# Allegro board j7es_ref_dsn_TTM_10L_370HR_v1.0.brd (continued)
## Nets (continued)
MCASP0_AFSX/SPI3_CS2: TPX130.1 U9.AB25(PRG0_PRU0_GPO10)
MCASP0_AXR0/PRG0_RGMII1_RD0: TPX54.1 U9.AF28(PRG0_PRU0_GPO0)
MCASP0_AXR1/PRG0_RGMII1_RD1: TPX5.1 U9.AE28(PRG0_PRU0_GPO1)
MCASP0_AXR2/PRG0_RGMII1_RX_CTL: TPX55.1 U9.AD25(PRG0_PRU0_GPO4)
MCASP0_AXR3: TPX183.1 U9.AC29(PRG0_PRU0_GPO5)
MCASP0_AXR4/PRG0_RGMII1_RXC: TPX29.1 U9.AE26(PRG0_PRU0_GPO6)
MCASP0_AXR5/MCAN9_TX: TPX158.1 U9.AC28(PRG0_PRU0_GPO7)
MCASP0_AXR6/MCAN9_RX: TPX132.1 U9.AC27(PRG0_PRU0_GPO8)
MCASP0_AXR7/PRG0_RGMII1_TD0: TPX28.1 U9.AJ28(PRG0_PRU0_GPO11)
MCASP0_AXR8/PRG0_RGMII1_TD1: TPX100.1 U9.AH27(PRG0_PRU0_GPO12)
MCASP0_AXR9/PRG0_RGMII1_TD2: TPX76.1 U9.AH29(PRG0_PRU0_GPO13)
MCASP0_AXR10/PRG0_RGMII1_TD3: TPX53.1 U9.AG28(PRG0_PRU0_GPO14)
MCASP0_AXR11/PRG0_RGMII1_TX_CTL: TPX75.1 U9.AG27(PRG0_PRU0_GPO15)
MCASP0_AXR12/PRG0_RGMII1_TXC: TPX4.1 U9.AH28(PRG0_PRU0_GPO16)
MCASP0_AXR13/PRG0_PWM0_B2: TPX110.1 U9.AB24(PRG0_PRU0_GPO17)
MCASP1_ACLKX: TPX83.1 U9.AB27(PRG0_PRU1_GPO5)
MCASP1_AFSX/MCAN11_RX: TPX82.1 U9.AA28(PRG0_PRU1_GPO8)
MCASP1_AXR0/PRG0_RGMII2_RD0: TPX129.1 U9.AE29(PRG0_PRU1_GPO0)
MCASP1_AXR1/PRG0_RGMII2_RD1: TPX179.1 U9.AD28(PRG0_PRU1_GPO1)
MCASP1_AXR2/PRG0_RGMII2_RX_CTL: TPX104.1 U9.AD29(PRG0_PRU1_GPO4)
MCASP1_AXR3/PRG0_RGMII2_RXC: TPX154.1 U9.AC26(PRG0_PRU1_GPO6)
MCASP1_AXR5/UART8_RXD: TPX181.1 U9.Y24(PRG0_PRU1_GPO9)
MCASP1_AXR6/UART8_TXD: TPX10.1 U9.AA25(PRG0_PRU1_GPO10)
MCASP1_AXR7/PRG0_RGMII2_TD0: TPX78.1 U9.AG26(PRG0_PRU1_GPO11)
MCASP1_AXR8/PRG0_RGMII2_TD1: TPX79.1 U9.AF27(PRG0_PRU1_GPO12)
MCASP2_ACLKX/SPI3_D1: TPX160.1 U9.AA29(PRG0_PRU1_GPO19)
MCASP2_AFSX/SPI3_D0: TPX159.1 U9.AA26(PRG0_PRU1_GPO18)
MCASP2_AXR3/SPI3_CLK: TPX134.1 U9.Y25(PRG0_PRU1_GPO17)
MCASP6_ACLKR/PRG1_RGMII1_RX_CTL: TPX148.1 U9.AH23(PRG1_PRU0_GPO4)
MCASP6_ACLKX/PRG1_RGMII1_RD0: TPX74.1 U9.AC23(PRG1_PRU0_GPO0)
MCASP6_AFSR/PRG1_RGMII1_RXC: TPX124.1 U9.AD22(PRG1_PRU0_GPO6)
MCASP6_AFSX/PRG1_RGMII1_RD1: TPX98.1 U9.AG22(PRG1_PRU0_GPO1)
MCASP6_AXR0/PRG1_RGMII1_RD2: TPX149.1 U9.AF22(PRG1_PRU0_GPO2)
MCU_ADC0_AIN0: TPX43.1 U9.K25(MCU_ADC0_AIN0)
MCU_ADC0_AIN1: TPX89.1 U9.K26(MCU_ADC0_AIN1)
MCU_ADC0_AIN2: TPX190.1 U9.K28(MCU_ADC0_AIN2)
MCU_ADC0_AIN3: TPX114.1 U9.L28(MCU_ADC0_AIN3)
MCU_ADC0_AIN4: TPX42.1 U9.K24(MCU_ADC0_AIN4)
MCU_ADC0_AIN5: TPX167.1 U9.K27(MCU_ADC0_AIN5)
MCU_ADC0_AIN6: TPX115.1 U9.K29(MCU_ADC0_AIN6)
MCU_ADC0_AIN7: TPX140.1 U9.L29(MCU_ADC0_AIN7)
MCU_ADC1_AIN0: TPX66.1 U9.N23(MCU_ADC1_AIN0)
MCU_ADC1_AIN1: TPX69.1 U9.M25(MCU_ADC1_AIN1)
MCU_ADC1_AIN2: TPX38.1 U9.L24(MCU_ADC1_AIN2)
MCU_ADC1_AIN3: TPX39.1 U9.L26(MCU_ADC1_AIN3)
MCU_ADC1_AIN4: TPX139.1 U9.N24(MCU_ADC1_AIN4)
MCU_ADC1_AIN5: TPX90.1 U9.M24(MCU_ADC1_AIN5)
MCU_ADC1_AIN6: TPX65.1 U9.L25(MCU_ADC1_AIN6)
MCU_ADC1_AIN7: TPX117.1 U9.L27(MCU_ADC1_AIN7)
MCU_ADC_EXT_TRIGGER0: TPX14.1 U9.H26(WKUP_GPIO0_10)
MCU_ADC_EXT_TRIGGER1: TPX118.1 U9.H27(WKUP_GPIO0_11)
MCU_CAN0_STBZ: R2102.1 U9.E28(MCU_SPI0_D1)
MCU_CAN1_STB: TPX324.1 U9.F28(WKUP_GPIO0_2)
MCU_HYPERBUS0_CS1#: R3137.1 U9.E22(MCU_OSPI1_CSN1)
MCU_HYPERBUS0_RESET#: U9.E19(MCU_OSPI0_CSN1)
MCU_HYPERBUS0_RESETO#: R138.2 R3136.1
MCU_I2C0_SCL: R74.2 U9.J26(MCU_I2C0_SCL) U27.32(GPIO1)
MCU_I2C0_SDA: R106.2 U9.H25(MCU_I2C0_SDA) U27.33(GPIO2)
MCU_I3C0_SCL: TPX70.1 U9.D26(MCU_I3C0_SCL)
MCU_I3C0_SDA: TPX94.1 U9.D25(MCU_I3C0_SDA)
MCU_I3C0_SDAPULLEN: TPX116.1 U9.E26(PMIC_POWER_EN0)
MCU_MCAN0_EN: TPX259.1 U9.F26(WKUP_GPIO0_0)
MCU_MCAN0_RX: R2109.1 U9.C29(MCU_MCAN0_RX)
MCU_MCAN0_TX: R2110.1 U9.D29(MCU_MCAN0_TX)
MCU_MCAN1_RX: TPX44.1 U9.G24(WKUP_GPIO0_5)
MCU_MCAN1_TX: TPX15.1 U9.G25(WKUP_GPIO0_4)
MCU_MDIO0_MDC: TPX137.1 U9.F23(MCU_MDIO0_MDC)
MCU_MDIO0_MDIO: TPX13.1 U9.E23(MCU_MDIO0_MDIO)
MCU_OSPI0_CLK: R247.2 R253.1 U24.B2(C)
MCU_OSPI0_CS0#: R153.1 U9.F19(MCU_OSPI0_CSN0) U24.C2(S#)
MCU_OSPI0_D0: R154.2 U9.D20(MCU_OSPI0_D0) U24.D3(DQ0)
MCU_OSPI0_D1: R149.2 U9.G19(MCU_OSPI0_D1) U24.D2(DQ1)
MCU_OSPI0_D2: R161.2 U9.G20(MCU_OSPI0_D2) U24.C4(DQ2/W#)
MCU_OSPI0_D3: R158.2 U9.F20(MCU_OSPI0_D3) U24.D4(DQ3)
MCU_OSPI0_D4: R162.2 U9.F21(MCU_OSPI0_D4) U24.D5(DQ4)
MCU_OSPI0_D5: R156.2 U9.E21(MCU_OSPI0_D5) U24.E3(DQ5)
MCU_OSPI0_D6: R150.2 U9.B22(MCU_OSPI0_D6) U24.E2(DQ6)
MCU_OSPI0_D7: R151.2 U9.G21(MCU_OSPI0_D7) U24.E1(DQ7)
MCU_OSPI0_DQS: R144.2 R152.2 U9.D21(MCU_OSPI0_DQS)
MCU_OSPI0_ECC_FAIL: R164.1 U9.B23(MCU_OSPI1_DQS)
MCU_OSPI0_LBCLKO: R264.2 R3140.1 U24.B1(RFU3)
MCU_OSPI0_RESET_OUT0: R108.1 R137.1
MCU_OSPI0_RESET_OUT0_R: R108.2 R114.1 U18.2(B)
MCU_OSPI1_CLK: R240.2 TPX68.1
MCU_OSPI1_CLK_R: R240.1 U9.F22(MCU_OSPI1_CLK)
MCU_OSPI1_CS0: TPX95.1 U9.C22(MCU_OSPI1_CSN0)
MCU_OSPI1_D0: TPX168.1 U9.D22(MCU_OSPI1_D0)
MCU_OSPI1_D1: TPX93.1 U9.G22(MCU_OSPI1_D1)
MCU_OSPI1_D2: TPX21.1 U9.D23(MCU_OSPI1_D2)
MCU_OSPI1_D3: TPX121.1 U9.C23(MCU_OSPI1_D3)
MCU_PERIPH_RSTZ: R109.1 TPX67.1
MCU_PERIPH_RSTZ_R: R109.2 R115.1 U18.1(A)
MCU_PORZ: TPX166.1 U9.H23(MCU_PORZ)
MCU_PORZ_OUT: R124.1 TP117.1(TP) U9.B28(MCU_PORZ_OUT)
MCU_RESETSTATZ: R113.1 TP116.1(TP) TPX92.1 U9.C27(MCU_RESETSTATZ)
MCU_RESETZ: TPX193.1 U9.D28(MCU_RESETZ)
MCU_RGMII1_INT#: TPX48.1 U9.E25(MCU_SPI0_CS0)
MCU_RGMII1_RD0: TPX80.1 U9.B24(MCU_RGMII1_RD0)
MCU_RGMII1_RD1: TPX87.1 U9.A24(MCU_RGMII1_RD1)
MCU_RGMII1_RD2: TPX88.1 U9.D24(MCU_RGMII1_RD2)
MCU_RGMII1_RD3: TPX107.1 U9.A25(MCU_RGMII1_RD3)
MCU_RGMII1_RX_CTL: TPX61.1 U9.C25(MCU_RGMII1_RX_CTL)
MCU_RGMII1_RXC: TPX64.1 U9.C24(MCU_RGMII1_RXC)
MCU_RGMII1_TD0: TPX106.1 U9.B25(MCU_RGMII1_TD0)
MCU_RGMII1_TD1: TPX108.1 U9.A26(MCU_RGMII1_TD1)
MCU_RGMII1_TD2: TPX131.1 U9.A27(MCU_RGMII1_TD2)
MCU_RGMII1_TD3: TPX187.1 U9.A28(MCU_RGMII1_TD3)
MCU_RGMII1_TX_CTL: TPX156.1 U9.B27(MCU_RGMII1_TX_CTL)
MCU_RGMII1_TXC: TPX105.1 U9.B26(MCU_RGMII1_TXC)
MCU_SAFETY_ERRZ: R120.2 U27.18(GPIO7)
MCU_UART0_CTS#: TPX214.1 U9.H29(WKUP_GPIO0_14)
MCU_UART0_RTS#: TPX215.1 U9.J27(WKUP_GPIO0_15)
MCU_UART0_RXD: TPX258.1 U9.H28(WKUP_GPIO0_13)
MCU_UART0_TXD: TPX319.1 U9.G29(WKUP_GPIO0_12)
MDIO0_MDC: U9.V24(MDIO0_MDC) U2011.1(MDC)
MDIO0_MDIO: U9.V26(MDIO0_MDIO) U2011.36(MDIO)
MLB0_MLBCLK_N: R209.2 TPX351.1 U9.AE2(MLB0_MLBCN)
MLB0_MLBCLK_P: R209.1 TPX352.1 U9.AD2(MLB0_MLBCP)
MLB0_MLBDAT_N: R215.2 TPX333.1 U9.AD3(MLB0_MLBDN)
MLB0_MLBDAT_P: R215.1 TPX334.1 U9.AC3(MLB0_MLBDP)
MLB0_MLBSIG_N: R217.2 TPX354.1 U9.AC1(MLB0_MLBSN)
MLB0_MLBSIG_P: R217.1 TPX353.1 U9.AD1(MLB0_MLBSP)
MMC0_CALPAD: R204.2 U9.AE1(MMC0_CALPAD)
MMC0_CLK: R1203.1 R1204.2 U9.AF1(MMC0_CLK)
MMC0_CMD: R1200.2 U9.AE3(MMC0_CMD) U1017.P5(CMD)
MMC0_DAT0: R1189.2 U9.AG2(MMC0_DAT0) U1017.K2(DAT0)
MMC0_DAT1: R1197.2 U9.AH1(MMC0_DAT1) U1017.N2(DAT1)
MMC0_DAT2: R1188.2 U9.AG3(MMC0_DAT2) U1017.K3(DAT2)
MMC0_DAT3: R1201.2 U9.AF4(MMC0_DAT3) U1017.N3(DAT3)
MMC0_DAT4: R1196.2 U9.AE5(MMC0_DAT4) U1017.N8(DAT4)
MMC0_DAT5: R1190.2 U9.AF3(MMC0_DAT5) U1017.K8(DAT5)
MMC0_DAT6: R1198.2 U9.AG1(MMC0_DAT6) U1017.N9(DAT6)
MMC0_DAT7: R1191.2 U9.AF2(MMC0_DAT7) U1017.K9(DAT7)
MMC0_DS: R3142.1 U9.AE4(MMC0_DS)
MMC0_RSTN: U1033.1(OE)
MMC1_CLK: TPX62.1 U9.P25(MMC1_CLK)
MMC1_CMD: TPX86.1 U9.R29(MMC1_CMD)
MMC1_DAT0: TPX136.1 U9.R24(MMC1_DAT0)
MMC1_DAT1: TPX162.1 U9.P24(MMC1_DAT1)
MMC1_DAT2: TPX111.1 U9.R25(MMC1_DAT2)
MMC1_DAT3: TPX85.1 U9.R26(MMC1_DAT3)
MMC1_SDCD/PCIE2_CLKREQN: R86.2 TPX189.1 U9.P23(MMC1_SDCD)
NTRST: J1011.9(NTRST) R1209.2 RJ1025.3
OSC1_XI: R67.1 U9.P29(OSC1_XI)
OSC1_XO: R77.1 U9.P27(OSC1_XO)
OSPI0_ECC_FAIL/MCU_HYPERBUS0_IN: R164.2 R3139.1 U24.A5(DNU1)
OSPI/HYPER_MUX_SEL: TPX238.1 U9.G27(WKUP_GPIO0_8)
OSPI_DQS_R: R152.1 U24.C3(DQS)
OSPI_RST#: U18.4(Y) U24.A4(RESET#)
PCIE0_RX0_N: TPX379.1 U9.AH19(SERDES0_RX0_N)
PCIE0_RX0_P: TPX378.1 U9.AJ18(SERDES0_RX0_P)
PCIE0_TX0_N: C227.2 TPX381.1
PCIE0_TX0_P: C226.2 TPX380.1
PCIE1_RX0_N: TPX449.1 U9.AH15(SERDES1_RX0_N)
PCIE1_RX0_P: TPX448.1 U9.AJ14(SERDES1_RX0_P)
PCIE1_RX1_N: TPX450.1 U9.AH16(SERDES1_RX1_N)
PCIE1_RX1_P: TPX451.1 U9.AJ15(SERDES1_RX1_P)
PCIE1_TX0_N: C224.2 TPX376.1
PCIE1_TX0_P: C225.2 TPX377.1
PCIE1_TX1_N: C223.2 TPX375.1
PCIE1_TX1_P: C222.2 TPX374.1
PCIE2_RX0_N: TPX455.1 U9.AH13(SERDES2_RX0_N)
PCIE2_RX0_P: TPX454.1 U9.AJ12(SERDES2_RX0_P)
PCIE2_RX1_N: TPX373.1 U9.AH12(SERDES2_RX1_N)
PCIE2_RX1_P: TPX372.1 U9.AJ11(SERDES2_RX1_P)
PCIE2_TX0_N: C213.2 TPX447.1
PCIE2_TX0_P: C212.2 TPX446.1
PCIE2_TX1_N: C221.2 TPX371.1
PCIE2_TX1_P: C220.2 TPX370.1
PG_LM5141: R1141.1 R3147.2 TP1010.1(TP) U1007.21(PG) U1022.6(EN)
PG_LM5175: C1059.2 R1033.2 R1135.1 TP1008.1(TP) U1008.17(PGOOD)
PG_LM53603: R1006.2 TP1005.1(TP) U1001.7(EN) U1005.8(RESETN)
PMIC_MCU_INT#_R: R93.1 U9.G26(WKUP_GPIO0_9)
PMIC_POWER_EN1: U9.G23(PMIC_POWER_EN1)
PMIC_PWR_EN1: R502.1 TP3019.1(TP)
PMIC_REGEN1_3V3_OD: U1008.1(EN/UVLO)
PMICB_EN: R280.2 U29.20(NPWRON/ENABLE)
PMICB_FB3: R3150.1 R3151.1 U29.49(FB_B3)
PMICB_FB4: R3148.1 R3149.1 U29.50(FB_B4)
PORZ: TPX282.1 U9.J24(PORZ)
PRG0_MDIO0_MDC: TPX161.1 U9.AA27(PRG0_MDIO0_MDC)
PRG0_MDIO0_MDIO: TPX133.1 U9.Y26(PRG0_MDIO0_MDIO)
PRG0_PWM0_TZ_OUT: TPX184.1 U9.AB28(PRG0_PRU0_GPO19)
PRG0_RGMII1_RD2: TPX30.1 U9.AE27(PRG0_PRU0_GPO2)
PRG0_RGMII1_RD3: TPX6.1 U9.AD26(PRG0_PRU0_GPO3)
PRG0_RGMII2_RD2: TPX103.1 U9.AD27(PRG0_PRU1_GPO2)
PRG0_RGMII2_RD3: TPX180.1 U9.AC25(PRG0_PRU1_GPO3)
PRG0_RGMII2_TD2: TPX31.1 U9.AF26(PRG0_PRU1_GPO13)
PRG0_RGMII2_TD3: TPX7.1 U9.AE25(PRG0_PRU1_GPO14)
PRG1_RGMII1_RD3: TPX174.1 U9.AJ23(PRG1_PRU0_GPO3)
PRG1_UART0_RTS#: TPX155.1 U9.AD21(PRG1_PRU0_GPO10)
PWR_SW_CNTL_DSI0: R3060.1 U3011.3(IN)
RESET_REQZ: TPX192.1 U9.C28(RESET_REQZ)
RESETSTATZ: R225.1 TPX208.1 U9.T6(RESETSTATZ)
RGMII5_RD0: U9.T23(RGMII5_RD0) U2011.26(RX_D0)
RGMII5_RD1: U9.R23(RGMII5_RD1) U2011.25(RX_D1)
RGMII5_RD2: U9.U24(RGMII5_RD2) U2011.24(RX_D2)
RGMII5_RD3: U9.U27(RGMII5_RD3) U2011.23(RX_D3)
RGMII5_RX_CTL: U9.U26(RGMII5_RX_CTL) U2011.15(RX_DV/CRS_DIV/RX_CTRL)
RGMII5_RXC: U9.U25(RGMII5_RXC) U2011.27(RX_CLK)
RGMII5_TD0: U9.U28(RGMII5_TD0) U2011.33(TX_D0)
RGMII5_TD1: U9.V27(RGMII5_TD1) U2011.32(TX_D1)
RGMII5_TD2: U9.V29(RGMII5_TD2) U2011.31(TX_D2)
RGMII5_TD3: U9.V28(RGMII5_TD3) U2011.30(TX_D3)
RGMII5_TX_CTL: U9.U23(RGMII5_TX_CTL) U2011.29(TX_EN/TX_CTRL)
RGMII5_TXC: U9.U29(RGMII5_TXC) U2011.28(TX_CLK)
SEL_SDIO_3V3_1V8N: U9.W4(SPI1_CS1)
SERDES0_REXT: R207.1 U9.AE18(SERDES0_REXT)
SERDES1_REXT: R206.1 U9.AE13(SERDES1_REXT)
SERDES2_REXT: R216.1 U9.AD13(SERDES2_REXT)
SERDES3_REXT: R205.1 U9.AE8(SERDES3_REXT)
SERDES4_REXT: R236.1 U9.F9(SERDES4_REXT)
SERDES4_RX0_N: TP43.1(TP) U9.D9(SERDES4_RX0_N)
SERDES4_RX0_P: TP42.1(TP) U9.C10(SERDES4_RX0_P)
SERDES4_RX1_N: TP36.1(TP) U9.D8(SERDES4_RX1_N)
SERDES4_RX1_P: TP35.1(TP) U9.C9(SERDES4_RX1_P)
SERDES4_RX2_N: TP39.1(TP) U9.D6(SERDES4_RX2_N)
SERDES4_RX2_P: TP37.1(TP) U9.C7(SERDES4_RX2_P)
SERDES4_RX3_N: TP40.1(TP) U9.D5(SERDES4_RX3_N)
SERDES4_RX3_P: TP38.1(TP) U9.C6(SERDES4_RX3_P)
SGMII2_RX0_N: TPX443.1 U9.AH18(SERDES0_RX1_N)
SGMII2_RX0_P: TPX442.1 U9.AJ17(SERDES0_RX1_P)
SGMII2_TX0_N: C215.2 TPX441.1
SGMII2_TX0_P: C214.2 TPX440.1
SOC_EMU0: J1011.19(TRD0.1) R1206.2 U9.C26(EMU0)
SOC_EMU1: J1011.21(TRD0.2) R1207.2 U9.B29(EMU1)
SOC_EXTINTN: R43.1 TPX206.1 U9.AC18(EXTINTN)
SOC_I2C2_SCL: R54.2 TPX296.1 U9.AA1(SPI0_CLK)
SOC_I2C2_SDA: R25.2 TPX203.1 U9.AB5(SPI0_D0)
SOC_MCU_OSPI0_CLK_R: R247.1 U9.E20(MCU_OSPI0_CLK)
SOC_MCU_OSPI0_LBCLKO_R: R264.1 U9.C21(MCU_OSPI0_LBCLKO)
SOC_PORZ_OUT: R80.1 TPX278.1 U9.U1(PORZ_OUT)
SOC_PWR_EN: R3147.1 TP128.1(TP) U27.20(NPWRON/ENABLE)
SOC_SAFETY_ERRZ: R56.2 TPX230.1
SOC_SAFETY_ERRZ_27020508: R276.1
SOC_SERDES0_REFCLK_N: R203.1 TPX392.1 U9.AE17(PCIE_REFCLK0N)
SOC_SERDES0_REFCLK_P: R213.1 TPX393.1 U9.AD16(PCIE_REFCLK0P)
SOC_SERDES1_REFCLK_N: R202.1 TPX423.1 U9.AE14(PCIE_REFCLK1N)
SOC_SERDES1_REFCLK_P: R208.1 TPX422.1 U9.AD15(PCIE_REFCLK1P)
SOC_SERDES2_REFCLK_N: R201.1 TPX427.1 U9.AE11(PCIE_REFCLK2N)
SOC_SERDES2_REFCLK_P: R214.1 TPX426.1 U9.AD12(PCIE_REFCLK2P)
SOC_SERDES4_REFCLK_N: TPX396.1 U9.E7(SERDES4_REFCLK_N)
SOC_SERDES4_REFCLK_P: TPX397.1 U9.E8(SERDES4_REFCLK_P)
SOC_TCK: J1011.3(TCK) R1208.2 R3135.2 U9.E29(TCK)
SOC_TDI: U9.V1(TDI) U131.4(O)
SOC_TDO: U9.V3(TDO) U130.2(I)
SOC_TMS: R1219.2 U9.V2(TMS) U129.4(O)
SOC_TRST#: RJ1025.2 U9.F24(TRSTN)
SOC_WKUP_I2C0_SCL: R105.2 U9.J25(WKUP_I2C0_SCL) U27.31(SCL_I2C1/SCK_SPI) U29.31(SCL_I2C1/SCK_SPI) U1011.6(SCL)
SOC_WKUP_I2C0_SDA: R121.2 U9.H24(WKUP_I2C0_SDA) U27.30(SDA_I2C1/SDI_SPI) U29.30(SDA_I2C1/SDI_SPI) U1011.5(SDA)
SPI3_CS0: TPX34.1 U9.AA24(PRG0_PRU1_GPO7)
SYS_IRQZ: TPX237.1 U9.G28(WKUP_GPIO0_7)
SYS_MCU_PWRDN: TPX211.1 U9.E24(MCU_SPI0_D0)
TIMER_IO0: TPX315.1 U9.V6(TIMER_IO0)
TRD1_N: C2029.1 JZ2000.2 R2025.1
TRD1_P: C2030.1 JZ2000.1 R2027.1
TRD_N: C2028.1 L2005.1 U2011.13(TRD_N)
TRD_P: C2031.1 L2007.1 U2011.12(TRD_P)
TRSTPD: J1011.8(TRSTPD) R1221.1 RJ1025.1
UART0_CTS#: TPX313.1 U9.Y3(SPI1_CS0)
UART0_RTS#: TPX274.1 U9.AA2(SPI0_CS0)
UART0_RXD: TPX337.1 U9.AB2(UART0_RXD)
UART0_TXD: TPX226.1 U9.AB3(UART0_TXD)
UART1_RXD: TPX249.1 U9.AA4(UART1_RXD)
UART1_TXD: TPX312.1 U9.AB4(UART1_TXD)
UART2_RXD: TPX298.1 U9.Y1(SPI1_CLK)
UART2_TXD: TPX248.1 U9.Y5(SPI1_D0)
UB981_CLKIN: R3102.2 R3103.2 R3104.2 TP3014.1(TP) U3019.41(REFCLK0)
UB981_CLKIN_25MHZ: R3104.1 U3020.3(OUTPUT)
UB981_DOUT0_N: C3121.2 FL3030.4
UB981_DOUT0_P: C3119.2 FL3030.1
UB981_GPIO0: U3019.14(GPIO0)
UB981_GPIO1: U3019.15(GPIO1)
UB981_GPIO2: U3019.38(I2S_DC/GPIO2)
UB981_GPIO3: U3019.39(I2S_DD/GPIO3)
UB981_IDX: R3112.1 R3113.2 U3019.19(IDX)
UB981_INTB: R3114.2 R3115.1 U3019.30(INTB)
UB981_MODE_SEL0: R3066.2 R3067.1 U3019.18(MODE_SEL0)
UB981_MODE_SEL1: R3065.2 R3111.1 U3019.32(MODE_SEL1)
UB981_PDB: R3110.1 U3019.31(PDB)
UB981_REM_INTB: R3105.1 U3019.10(REM_INTB)
UFS0_REF_CLK: R168.1 TPX390.1
UFS0_REF_CLK_R: R168.2 U9.AE6(UFS0_REF_CLK)
UFS0_RST#: TPX391.1 U9.AD6(UFS0_RSTN)
UFS0_RX0_N: TPX386.1 U9.AH3(UFS0_RX_DN0)
UFS0_RX0_P: TPX387.1 U9.AJ2(UFS0_RX_DP0)
UFS0_RX1_N: TPX388.1 U9.AH4(UFS0_RX_DN1)
UFS0_RX1_P: TPX389.1 U9.AJ3(UFS0_RX_DP1)
UFS0_TX0_N: TPX385.1 U9.AG6(UFS0_TX_DN0)
UFS0_TX0_P: TPX384.1 U9.AF7(UFS0_TX_DP0)
UFS0_TX1_N: TPX383.1 U9.AG5(UFS0_TX_DN1)
UFS0_TX1_P: TPX382.1 U9.AF6(UFS0_TX_DP1)
USB0_CS: R1010.1
USB0_DATA_N: U9.AJ5(USB0_DM) U1001.4(DM_OUT)
USB0_DATA_P: U9.AH6(USB0_DP) U1001.5(DP_OUT)
USB0_DRVVBUS: R1007.1 R1008.1 R1011.1 U9.U6(USB0_DRVVBUS)
USB0_ID: R3122.1 U9.AC6(USB0_ID)
USB0_IMON: C1017.1 R1005.1 TP1002.1(TP) U1001.1(IMON)
USB0_RCALIB: R218.1 U9.AB6(USB0_RCALIB)
USB0_STATUS: R1001.1 U1001.17(STATUS)
USB0_VBUS_OCN: R1002.1 U1001.18(FAULT)
USB0_VBUS_SOC: R169.2 R170.2 U9.AC7(USB0_VBUS)
USB1_CS: C1194.1 R1127.2 R1130.1
USB1_DM: FL1001.1 U1001.14(DM_IN)
USB1_DP: FL1001.4 U1001.13(DP_IN)
USB1_DRVVBUS: Q1001.2(G2) R1009.1 U9.V4(MCAN1_TX)
USB1_HUB_D_N: U9.AH7(USB1_DM) U1002.12(D-)
USB1_HUB_D_P: U9.AJ6(USB1_DP) U1002.11(D+)
USB1_ID: R3123.1 U9.AD7(USB1_ID)
USB1_RCALIB: R210.1 U9.AD9(USB1_RCALIB)
USB1_VBUS: C1006.2 J1001.1(VBUS) R4.1 U1002.2(VBUS_CON) U1002.3(VBUS_SON)
USB1_VBUS_SOC: R1.1 R4.2 U9.AD8(USB1_VBUS)
USB2_DM: FL1000.4 U1002.5(VD-)
USB2_DP: FL1000.1 U1002.6(VD+)
USBC_DIR: TPX294.1 U9.W3(MCAN1_RX)
USBC_SS_RX1_N: FL3028.4 U9.AH10(SERDES3_RX1_N)
USBC_SS_RX1_P: FL3028.1 U9.AJ9(SERDES3_RX1_P)
USBC_SS_RX2_N: FL1002.4 U9.AH9(SERDES3_RX0_N)
USBC_SS_RX2_P: FL1002.1 U9.AJ8(SERDES3_RX0_P)
USBC_SS_TX1_N: C219.2 FL3029.4
USBC_SS_TX1_P: C218.2 FL3029.1
USBC_SS_TX2_N: C217.2 FL1003.4
USBC_SS_TX2_P: C216.2 FL1003.1
VCAM_9V0: C234.1 C249.1 C3129.1 C3130.1 C3135.1 C3136.1 C3141.1 C3142.1 L51.2 L2018.2 L2024.2 L2030.2
VCAM_CSI: U3022.21(VDD_CSI0) U3022.33(VDD_CSI1)
VCAM_FPD: U3022.52(VDD_FPD1) U3022.61(VDD_FPD2)
VCAM_VDD18: U3022.1(VDD18_P3) U3022.2(VDD18_P2) U3022.47(VDD18_P1) U3022.48(VDD18_P0)
VCAM_VDD18_FPD: U3022.49(VDD18_FPD0) U3022.55(VDD18_FPD1) U3022.58(VDD18_FPD2) U3022.64(VDD18_FPD3)
VCAM_VDDA18: U3022.32(VDDA18A)
VCAM_VDDL: U3022.13(VDDL1) U3022.44(VDDL2)
VCAP_MCU_VDDS0: C372.1 U9.K23(CAP_VDDS0_MCU)
VCAP_MCU_VDDS1: C377.1 U9.J18(CAP_VDDS1_MCU)
VCAP_MCU_VDDS2: C379.1 U9.J19(CAP_VDDS2_MCU)
VCAP_VDDS0: C307.1 U9.U7(CAP_VDDS0)
VCAP_VDDS1: C278.1 U9.AB21(CAP_VDDS1)
VCAP_VDDS2: C291.1 U9.Y18(CAP_VDDS2)
VCAP_VDDS3: C293.1 U9.W21(CAP_VDDS3)
VCAP_VDDS4: C281.1 U9.AA22(CAP_VDDS4)
VCAP_VDDS5: C325.1 U9.R22(CAP_VDDS5)
VCAP_VDDS6: C306.1 U9.V22(CAP_VDDS6)
VDA_DLL_0V8: C512.1 FL6.1 FL15.1 FL29.1 U27.9(VOUT_LDO3)
VDA_MCU_1V8: C104.1 C111.1 C122.1 C131.1 C296.1 C314.1 C348.1 C349.1 C369.1 C370.1 C425.1 C511.1 R272.2 R493.2 U9.G18(VDDA_MCU_PLLGRP0) U9.H22(VDDA_WKUP) U9.M23(VDDA_ADC1) U9.N22(VDDA_ADC0) U9.P21(VDDA_MCU_TEMP) U9.P22(VDDA_POR_WKUP) U27.7(VOUT_LDO4)
VDA_PLL_1V8: C105.1 C112.1 C238.1 C239.1 C295.1 C300.1 C313.1 C428.1 C429.1 C543.1 U9.H9(VDDA_TEMP2_3) U9.L12(VDDA_PLLGRP3) U9.M17(VDDA_PLLGRP2) U9.P9(VDDA_PLLGRP5) U9.R11(VDDA_PLLGRP4) U9.R21(VDDS_OSC1) U9.W15(VDDA_TEMP0_1) U9.W17(VDDA_PLLGRP1) U9.W18(VDDA_PLLGRP6) U9.Y20(VDDA_PLLGRP0) U29.7(VOUT_LDO4)
VDA_USB_3V3: C34.1 C35.1 C545.1 U9.AB10(VDDA_3P3_USB) U29.11(VOUT_LDO2)
VIO_3V3: R1033.1
VMON_VEXT: TP127.1(TP) U9.V19(VMON_IR_VEXT)
VMON_VSYS: C132.1 R84.2 R87.1 U9.M26(VMON_ER_VSYS)
VOSNS: C1061.2 R1039.2 U1008.12(VOSNS)
VOUT0_DATA0/PRG1_RGMII2_RD0: TPX150.1 U9.AE22(PRG1_PRU1_GPO0)
VOUT0_DATA1/PRG1_RGMII2_RD1: TPX126.1 U9.AG23(PRG1_PRU1_GPO1)
VOUT0_DATA2/PRG1_RGMII2_RD2: TPX177.1 U9.AF23(PRG1_PRU1_GPO2)
VOUT0_DATA3/PRG1_RGMII2_RD3: TPX127.1 U9.AD23(PRG1_PRU1_GPO3)
VOUT0_DATA4/PRG1_RGMII2_RX_CTL: TPX101.1 U9.AH24(PRG1_PRU1_GPO4)
VOUT0_DATA5/MCAN6_RX: TPX175.1 U9.AG21(PRG1_PRU1_GPO5)
VOUT0_DATA6/PRG1_RGMII2_RXC: TPX151.1 U9.AE23(PRG1_PRU1_GPO6)
VOUT0_DATA7/MCAN7_TX: TPX50.1 U9.AC21(PRG1_PRU1_GPO7)
VOUT0_DATA8/MCAN7_RX: TPX186.1 U9.Y23(PRG1_PRU1_GPO8)
VOUT0_DATA9/PRG1_UART0_RXD: TPX125.1 U9.AF21(PRG1_PRU1_GPO9)
VOUT0_DATA10/PRG1_UART0_TXD: TPX58.1 U9.AB23(PRG1_PRU1_GPO10)
VOUT0_DATA11/PRG1_RGMII2_TD0: TPX26.1 U9.AJ25(PRG1_PRU1_GPO11)
VOUT0_DATA12/PRG1_RGMII2_TD1: TPX73.1 U9.AH25(PRG1_PRU1_GPO12)
VOUT0_DATA13/PRG1_RGMII2_TD2: TPX25.1 U9.AG25(PRG1_PRU1_GPO13)
VOUT0_DATA14/PRG1_RGMII2_TD3: TPX3.1 U9.AH26(PRG1_PRU1_GPO14)
VOUT0_DATA15/PRG1_RGMII2_TX_CTL: TPX27.1 U9.AJ27(PRG1_PRU1_GPO15)
VOUT0_DATA16/PRG1_RGMII1_TD0: TPX178.1 U9.AF24(PRG1_PRU0_GPO11)
VOUT0_DATA17/PRG1_RGMII1_TD1: TPX77.1 U9.AJ24(PRG1_PRU0_GPO12)
VOUT0_DATA18/PRG1_RGMII1_TD2: TPX102.1 U9.AG24(PRG1_PRU0_GPO13)
VOUT0_DATA19/PRG1_RGMII1_TD3: TPX153.1 U9.AD24(PRG1_PRU0_GPO14)
VOUT0_DATA20/PRG1_RGMII1_TX_CTL: TPX128.1 U9.AC24(PRG1_PRU0_GPO15)
VOUT0_DATA21/PRG1_RGMII1_TXC: TPX152.1 U9.AE24(PRG1_PRU0_GPO16)
VOUT0_DATA22/MCAN4_RX: TPX147.1 U9.AJ20(PRG1_PRU0_GPO8)
VOUT0_DATA23/SPI6_CS1: TPX72.1 U9.AG20(PRG1_PRU0_GPO9)
VOUT0_DE/SPI6_CLK: TPX63.1 U9.AC22(PRG1_PRU1_GPO17)
VOUT0_EXTPCLKIN/MCAN6_TX: TPX173.1 U9.AH21(PRG1_PRU0_GPO19)
VOUT0_HSYNC/PRG1_RGMII2_TXC: TPX2.1 U9.AJ26(PRG1_PRU1_GPO16)
VOUT0_PCLK/SPI6_D1: TPX176.1 U9.AH22(PRG1_PRU1_GPO19)
VOUT0_VSYNC/SPI6_D0: TPX123.1 U9.AJ22(PRG1_PRU1_GPO18)
VPFE0_DATA6/MCAN5_TX: TPX97.1 U9.AJ21(PRG1_PRU0_GPO17)
VPFE0_DATA7/MCAN5_RX: TPX99.1 U9.AE21(PRG1_PRU0_GPO18)
VPFE0_DATA11/PRG1_MDIO0_MDIO: TPX1.1 U9.AD19(PRG1_MDIO0_MDIO)
VPFE0_DATA12/PRG1_MDIO0_MDC: TPX49.1 U9.AD18(PRG1_MDIO0_MDC)
VPP_EFUSE_1V8: C57.1(INPUT) C57.3(OUTPUT) C58.1(INPUT) C58.3(OUTPUT) C279.1 C385.1 U9.AB11(VPP_CORE) U9.F17(VPP_MCU)
VRTC_LEOA_1V8: C510.1 U27.3(VOUT_LDOVRTC)
VRTC_LEOB_1V8: C542.1 R3144.1 U29.3(VOUT_LDOVRTC)
VSYS_3V3: C86.1 C88.1 C1044.1 C1045.1 C1136.1 C1205.1 C3145.1 L1005.2 L1023.1 R84.1 R472.1 R625.1 R1022.2 R1023.2 R1141.2 U6.1(VIN1) U6.2(VIN2) U6.4(VBIAS) U103.5(D) U129.5(VCC) U130.5(VCC) U131.5(VCC) U1022.4(ILM) U1022.8(VIN)
VSYS_5V0: C1145.1 C1146.1 C1161.1 C2121.1 R1071.2 R1074.2 TP1037.1(TP) U1007.16(VCCX) U1022.2(VOUT) U2007.3(VCC)
VSYS_10V5: C1182.1 C1183.1 L1040.2 R1106.2 TP1040.1(TP) U1008.24(BIAS)
VSYS_16V0: C1007.2 C1010.1 C1015.2 C1032.1 C1034.1 C1187.1 C1200.2 C1201.1 C1202.1 J1010.1 Q1006.5(D) R1038.2 R1039.1 R1110.1 TP1006.1(TP) U1005.12(VIN1) U1005.13(VIN2) U1027.7(VIN)
VSYS_SENSE: D2.1(CATHODE) R473.2 U27.51(VSYS_SENSE)
VUB941_1V1: C3054.1 C3061.1 C3063.1 FL3012.1 FL3013.1 FL3014.1
VUSB_5V0: C1011.1 C1012.1 C1016.1 C1018.1 C1020.1 C1024.1 C1194.2 C1197.1 L1002.2 R1006.1 R1125.1 R1127.1 R1137.2 TP1001.1(TP) U1001.2(IN#2) U1001.3(IN#3) U1002.14(VBUS_SYS#14) U1002.15(VBUS_SYS#15)
WKUP_GPIO0_6: TPX18.1 U9.F29(WKUP_GPIO0_6)
WKUP_GPIO0_52: TPX253.1 U9.E27(MCU_SPI0_CLK)
WKUP_LFOSC_XI: R88.1 R281.1 U9.N28(WKUP_LFOSC0_XI)
WKUP_LFOSC_XO: R89.1 U9.N26(WKUP_LFOSC0_XO)
WKUP_OSC0_XIN: C135.1 U9.M29(WKUP_OSC0_XI) Y3.3
WKUP_OSC0_XOUT: C136.1 U9.M27(WKUP_OSC0_XO) Y3.1
WKUP_UART0_RXD: TPX191.1 U9.J29(WKUP_UART0_RXD)
WKUP_UART0_TXD: TPX165.1 U9.J28(WKUP_UART0_TXD)
N22073312: R1203.2 U1017.P6(CLK)
N23139394: D1.3(C) R170.1 R171.2
N23154802: R120.1 U9.D27(MCU_SAFETY_ERRORN)
N24377130: R56.1 U9.U4(SOC_SAFETY_ERRORN)
N24594267: R137.2 R138.1 U9.A23(MCU_OSPI1_LBCLKO)
N27191474: R471.2 U27.52(OVPGDRV)
N27191486: R471.1 U103.4(GATE)
N27191539: R472.2 R473.1
N28200806: C125.1 R88.2 Y2.2
N28200825: C124.1 R89.2 Y2.1
N28200987: C110.1 R67.2 Y1.3
N28201033: C114.1 R77.2 Y1.1
N28832809: C3125.2 R3124.1
N28833063: C228.1 C3126.1 L40.2 L51.1 R3125.2
N28833077: L27.2 L40.1 R132.2 R3125.1
N28833083: L27.1 L62.2 R132.1
N28833091: L61.2 L62.1
N28833093: L60.2 L61.1
N28833539: C3124.2 L60.1 P5.1
N28846480: L2021.2 L2022.1 R3126.1
N28846484: L2022.2 L2023.1 R3126.2 R3127.1
N28846490: C3127.1 C3128.1 L2018.1 L2023.2 R3127.2
N28846519: C3131.2 L2019.1 P6.1
N28846523: L2019.2 L2020.1
N28846525: L2020.2 L2021.1
N28846680: C3132.2 R3128.1
N28847093: L2027.2 L2028.1 R3129.1
N28847097: L2028.2 L2029.1 R3129.2 R3130.1
N28847103: C3133.1 C3134.1 L2024.1 L2029.2 R3130.2
N28847132: C3137.2 L2025.1 P7.1
N28847136: L2025.2 L2026.1
N28847138: L2026.2 L2027.1
N28847293: C3138.2 R3131.1
N28847739: L2033.2 L2034.1 R3132.1
N28847743: L2034.2 L2035.1 R3132.2 R3133.1
N28847749: C3139.1 C3140.1 L2030.1 L2035.2 R3133.2
N28847778: C3143.2 L2031.1 P8.1
N28847782: L2031.2 L2032.1
N28847784: L2032.2 L2033.1
N28847939: C3144.2 R3134.1
N28898333: J1011.1(VREF_DBG) J1011.12(VREF_TR) R3143.2
N28898472: J1011.7(RTCK) R3135.1
N28898495: J1011.15(TGT_DETECT) R1205.2
N28916086: Q13.D R625.2 U129.1(OE) U130.1(OE) U131.1(OE)
N28916647: R3136.2 U24.A2(RFU1)
N28916666: R3137.2 R3138.1 U24.A3(RFU2)
N28964551: R3141.1 R3142.2 U1017.K5(DS)
N28998069: TP3015.1(TP) U9.F13(TEMP_DIODE_P)
N29139280: R3144.2 U29.40(OSC32KCAP)
N29153603: R3148.2 TP3020.1(TP)
N29154086: R3150.2 TP3021.1(TP)
N30074897: R1133.1 U1002.16(IADJ)
N30074992: R1134.2 TP1003.1(TP) U1002.10(FLT)
N30075038: Q1001.6(D2) R1125.2 U1002.7(VEN)
N30075044: R1126.2 U1002.8(DEN)
N30411655: R1164.1 TP1018.1(TP) U1011.7(WP)
N30703324: C1005.1 R1000.2 U1001.12(BIAS)
N30703458: R1003.1 U1001.19(ILIM_LO)
N30703463: R1004.1 U1001.20(ILIM_HI)
N30746595: RJ1000.2 U1001.10(OVP_SEL)
N30808408: L1023.2 U1022.7(SW)
N30809211: C1161.2 R1071.1 R1072.2 U1022.3(FB)
N30811250: R1109.1 R1110.2 RJ1013.2 U1027.5(EN/SYNC)
N30811520: C1190.1 U1027.3(VCC)
N30812987: C1189.1 U1027.2(BOOT)
N30812990: C1189.2 R1091.1
N30812993: L1040.1 R1091.2 U1027.1(SW)
N30813342: C1191.1 R1107.1 R1108.1 U1027.4(FB)
N30813649: C1191.2 R1106.1 R1107.2
N30821669: R1074.1 U1022.5(PG)
N31193882: Q1005.4(G) R1014.1
N31194203: Q1003.4(G) R1020.1
N31194290: Q1004.4(G) R1021.2
N31194295: Q1006.4(G) R1015.2
N31194655: D1008.1(CATHODE) R1034.1
N31194670: C1063.1 R1034.2 U1008.2(VIN)
N31194787: C1049.1 D1007.1(K) U1008.26(BOOT1)
N31194818: C1046.2 D1003.1(CATHODE) D1005.1(K) U1008.20(BOOT2)
N31196095: C1053.2 R1030.1 U1008.15(CSG)
N31196104: C1053.1 R1031.1 U1008.16(CS)
N31196146: C1069.1 U1008.7(SLOPE)
N31196169: R1046.1 U1008.5(DTH)
N31196187: C1071.2 R1042.1 U1008.6(RT/SYNC)
N31196205: R1040.1 R1045.1 U1008.4(MODE)
N31196259: C1065.1 R1036.2 U1008.9(COMP)
N31196266: C1064.1 R1036.1
N31197066: C1070.1 U1008.8(SS)
N31197134: C1062.2 R1037.2 U1008.3(VISNS)
N31197473: R1035.2 R1038.1 TP1012.1(TP)
N31206842: Q1002.4(G) U1006.2(GT PULL DWN) U1006.6(GATE DRV)
N31206856: C1029.1 U1006.1(VCAPL)
N31206860: C1029.2 U1006.7(VCAPH)
N31206880: C1021.1 C1022.1 L1003.1 L1004.1 Q1002.5(D1) R1131.2 U1006.8(CATHODE)
N31207093: D1018.2(ANODE) D1019.2(ANODE)
N31207095: DS1000.2(ANODE) R1131.1
N31208453: R1139.2 U1007.13(HO)
N31208462: R1140.1 U1007.14(HOL)
N31208471: R1144.2 U1007.8(LO)
N31208480: R1145.1 U1007.7(LOL)
N31208503: Q1008.4(G) R1144.1 R1145.2
N31208524: Q1007.4(G) R1139.1 R1140.2
N31208551: C1037.1 C1204.2 D1020.1(CATHODE) L1005.1 Q1007.1(S) Q1008.5(D) R1017.1 U1007.12(SW)
N31208672: C1037.2 D1004.1(CATHODE) U1007.11(HB)
N31208960: C1204.1 R1152.1
N31209649: C1033.2 R1017.2 R1018.1 U1007.18(CS)
N31209654: C1033.1 R1018.2 R1022.1 U1007.17(VOUT)
N31222073: C1047.2 R1142.1 R1143.1 U1007.23(EN)
N31222132: C1039.2 R1026.1
N31222198: C1038.1 R1026.2 U1007.20(COMP)
N31222241: C1050.2 U1007.24(RES)
N31222246: C1041.2 U1007.22(SS)
N31222265: R1028.1 R1029.2 U1007.6(OSC)
N31222285: C1052.2 R1027.1 U1007.5(DITH)
N31222303: R1147.2 U1007.4(RT)
N31222717: R1023.1 R1024.2
N31223527: L1002.1 R1013.2 R1136.1 R1138.1 U1005.1(SW1) U1005.2(SW2)
N31223584: C1026.1 R1137.1 U1005.5(BIAS)
N31223889: C1025.2 R1013.1
N31224124: R1130.2 R1132.1 U1005.9(FB)
N31225374: R1010.2 U1001.6(CS)
N31225630: R1135.2 U1005.11(EN)
N31225660: R1016.1 RJ1001.2 U1005.6(SYNC)
N31226612: C1027.2 U1005.4(VCC) U1005.7(FPWM)
N31251157: C2027.1 C2028.2 R2024.2
N31251611: L2005.2 L2006.3 R2024.1 U2010.1(IO)
N31252401: L2006.4 L2007.2 R2030.1 U2012.1(IO)
N31252434: C2031.2 C2034.1 R2030.2
N31269356: C2085.1 L2017.1 U2023.1(OUT)
N31279750: R2008.2 SW2001.3(B) SW2001.4(BB)
N31313642: R1007.2 U1001.8(CTL1)
N31313645: R1008.2 U1001.9(CTL2)
N31555915: C1199.1 R1136.2 R1138.2
N31730797: C1008.1 D1002.CATHODE L1000.1
N33657189: C2035.2 R2025.2 R2027.2 R2032.2
N33657272: C2030.2 L2006.1
N33657370: C2029.2 L2006.2
N33657483: C2127.1 U2011.5(XI) Y2000.3(C1)
N33657512: C2126.1 U2011.4(XO) Y2000.1(Y1)
N33657557: R2115.2 U2011.2(INT_N)
N33657559: TP2000.1(TP) U2011.16(CLK_OUT/GPIO_2)
N33658409: R2106.2 R2107.1 U2007.7(INH)
N33658469: R2099.2 R2100.2 U2007.8(NFAULT)
N33658487: R2105.2 R2108.2 U2007.6(EN)
N33658532: R2102.2 R2103.2 U2007.14(NSTB)
N33658660: R2101.1 U2007.9(WAKE)
N33658666: C2116.1 R2098.2 R2104.1
N33658711: R2109.2 U2007.4(RXD)
N33658728: R2110.2 U2007.1(TXD)
N289339640: C1025.1 U1005.3(CBOOT)

Pads without a net: D1 2; FL* 1 2 3 4; J1011 10 11 13 14 17 18 20 22 23 24 25 26 27 28 29 30 31 32 33 34 35 36 37 38 39 40 41 42 43 44 45 46 47 48 49 50 51 52 53 54 55 56 59 60; JZ2000 7 8 9 13 14; Q1001 3 4 5; R* 1 2; U9 AA23 AD4 AJ29 E6 E18 F6 F10 F11 F18 G9 G10 L6 N6 N25 P26 R27; U11 A1 A2 A11 A12 AA1 AA12 AB1 AB2 AB11 AB12 B1 B12 G11 K5 K8 N5 N8; U24 B5 C5; U27 1; U29 1 25 29 39 51 52; U1002 1; U1005 14; U1006 3 5; U1017 A1 A2 A9 A10 B1 B10 D2 D3 D4 D5 D6 D7 D8 D9 E2 E3 E5 E6 E7 E8 E9 H4 H5 H6 H7 J2 J3 J4 J6 J7 J8 J9 K4 K6 K7 L5 L6 M2 M3 M6 M8 M9 N4 N5 N6 N7 P4 P7 T1 T10 U1 U2 U9 U10; U2007 11; U2011 6 14 17 18 19 20 35; U2023 2; U3011 1 4 11 14; U3019 11 13 22 23 34 35 36 37 43 44 45 46; U3022 3 4 5 6 7 8 9 10 11 12 14 15 17 18 19 20 34 35 36 37 38 39 40 41 42 43 45 46 56 57

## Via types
v1: diameter 0.457, hole 0.203, TOP to BOTTOM, 1949 vias
v2: diameter 0.508, hole 0.254, TOP to BOTTOM, 1148 vias
v3: diameter 0.635, hole 0.305, TOP to BOTTOM, 12 vias
v4: diameter 0.61, hole 0.305, TOP to BOTTOM, 2 vias

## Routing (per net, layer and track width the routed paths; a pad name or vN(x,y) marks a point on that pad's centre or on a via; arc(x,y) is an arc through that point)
1V8_RSTOUTN: length 8.6
  TOP w0.229: U1017.M5 v2(149.66,86.21)
  L7-SIGNAL w0.097: v2(149.66,86.21) 149.26,86.61 149.26,87.38 149.43,87.55 149.43,91.61 v2(149.1,91.94)
  BOTTOM w0.127: v2(149.66,86.21) 149.9,85.97 R1192.1
  BOTTOM w0.14: v2(149.1,91.94) 148.74,92.29 U1033.4
DGND: length 837.5
  TOP w0.089: U11.G12 122.85,63.86 123.8,63.86 U11.G10
  TOP w0.102: U9.U19 95.45,73.35
  TOP w0.203: v2(75.95,72.34) 75.63,72.67 Y1.2 ; Y3.2 76.7,65.05 v2(76.96,65.32) ; R1030.2 v2(183.39,58.28) ; Y3.4 72.66,66.25 v2(72.39,65.98) ; v2(73.65,74.19) 73.98,73.87 Y1.4 ; C70.2 v2(113.03,88.76)
  TOP w0.229: v1(90.25,80.95) 90.65,80.55 U9.AF25 ; U27.21 v1(126.47,97.65) ; U9.AF20 94.65,80.55 v1(94.25,80.95) ; J3003.2 v1(138.72,12) ; U29.21 v1(76.7,111.27)
  TOP w0.254: U6.5 157.65,110.32 v2(157.66,110.33) ; v2(170.55,128) 170.55,128.01 170.69,128.01 C1018.2 ; J3003.19 130.22,11.73 v1(130,11.51) ; J3003.16 131.72,11.59 v1(131.87,11.44) ; C96.2 v2(153.31,106.54) ; U1001.11 v2(175.5,133.87) ; C89.2 v2(156.08,111.37) ; J3003.8 v1(135.72,11.88) ; C88.2 157.04,107.49 v2(156.84,107.69) ; R1019.2 v2(174.37,67.17) ; J3003.11 v1(134.22,11.88) ; J3003.5 v1(137.22,11.88)
  TOP w0.305: v1(95.05,83.35) 95.45,82.95 U9.AJ19 ; U9.B12 101.05,61.35 v1(101.45,60.95) ; U11.P1 131.33,68.08 v1(131.73,67.76) ; 122.16,26.56 122.16,25.26 v1(122.66,24.76) ; 122.16,26.56 v1(122.67,26.04) ; 122.16,26.56 C3058.2 ; C1017.2 v2(168.02,128.51) ; v1(93.46,76.15) 93.86,75.75 U9.Y21 ; U2007.2 v2(40,36.57) ; U9.M14 99.45,69.35 v1(99.85,68.95) ; v1(122.13,69.06) 122.53,69.38 U11.T12 ; v1(114.81,32.16) C3051.2 114.81,32.95 ; U9.M1 109.85,69.35 v1(110.25,68.95) ; R1004.2 v2(168.02,130.8) ; v1(95.05,62.55) 95.45,62.95 U9.D19 ; U1017.L8 v2(150.66,82.2) ; v1(95.06,77.75) 95.46,77.35 U9.AB19 ; U9.J13 100.25,66.95 v1(100.65,66.55) ; U9.V18 v1(95.85,74.55) ; v1(110.25,64.95) 109.85,65.35 U9.G1 ; U9.B9 103.45,61.35 v1(103.85,60.95) ; U9.P14 v1(99.85,70.55) ; U9.AG16 97.85,81.35 v1(97.45,81.75) ; U1002.13 161.35,126.29 v2(161.67,125.97) ; v1(103.85,76.95) 103.45,76.55 U9.AA9 ; U11.J12 v1(122.13,64.51) ; U11.V1 131.33,70.68 v1(130.93,70.36) ; Y2000.2 v2(48.84,48.58) ; v1(85.6,92.57) C41.2 v1(86.36,92.57) ; v1(96.65,66.55) 97.05,66.95 U9.J17 ; U9.AH17 97.05,82.15 v1(96.65,82.55) ; U9.Y12 101.05,75.75 v1(101.45,76.15) ; U9.AC16 97.85,78.15 v1(97.45,78.55) ; v1(95.85,67.35) 96.25,67.75 U9.K18 ; U9.AA11 101.85,76.55 v1(102.25,76.95) ; v1(105.45,83.35) 105.05,82.95 U9.AJ7 ; U11.AB8 125.73,73.28 v1(126.13,73.76) ; U9.L19 95.45,68.55 v1(95.05,68.15) ; v1(131.73,72.31) 131.33,71.98 U11.Y1 ; v1(97.45,67.35) 97.85,67.75 U9.K16 ; v1(109.45,82.55) 109.05,82.15 U9.AH2 ; U9.N21 93.85,70.15 v1(93.45,69.75) ; v1(99.05,82.55) 99.45,82.15 U9.AH14 ; v1(109.96,20.52) 109.96,20.52 109.96,19.61 C3069.2 ; U9.A13 v1(100.65,60.14) ; v1(105.45,81.75) 105.05,81.35 U9.AG7 ; U1022.1 23.86,16.56 v4(23.55,16.25) ; v1(100.65,83.35) 100.25,82.95 U9.AJ13 ; v1(128.53,69.06) 128.13,69.38 U11.T5 ; U9.K4 v1(107.85,67.35) ; C3070.2 111,20.19 v1(111.33,20.52) ; C30.2 v2(101.54,100.57) ; U9.R13 100.25,71.75 v1(100.65,71.35) ; U11.AB5 v1(128.13,73.82) ; U9.R15 98.65,71.75 v1(98.25,71.35) ; U11.G1 v1(131.73,63.86) ; U9.AG19 95.45,81.35 v1(95.05,81.75) ; U9.AE19 95.45,79.75 v1(95.05,80.15) ; U9.H8 v1(104.65,65.75) ; v2(188.34,97.27) 188.85,97.27 189.28,96.84 C1028.2 189.28,96.69 188.85,96.26 v2(188.34,96.26) ; U9.R9 103.45,71.75 v1(103.85,71.35) ; U11.W4 128.93,71.33 128.13,71.98 ; U9.C14 v1(99.85,61.75) ; U9.L3 v1(108.65,68.15) ; v1(107.85,83.35) 107.45,82.95 U9.AJ4 ; U9.AD14 99.45,78.95 v1(99.05,79.35) ; U1017.G5 v2(155.66,86.21) ; v1(104.65,68.95) 104.25,69.35 U9.M8 ; v1(127.07,61.97) 127.17,62.07 127.97,62.07 U11.E5 ; U9.W11 101.85,74.95 v1(102.25,75.35) ; v1(107.85,68.95) 107.45,69.35 U9.M4 ; U11.J3 v1(130.13,65.16) U11.K2 ; C3062.2 101.34,26.2 v1(101.22,26.31) ; U11.N2 130.53,67.43 v1(130.13,67.76) 129.73,68.08 U11.P3 ; v1(98.25,60.95) 98.65,61.35 U9.B15 ; C132.2 v2(81.51,66.54) ; v1(97.45,72.15) 97.85,72.55 U9.T16 ; C571.2 v2(113.54,99.94) ; v1(93.46,73.75) 93.86,73.35 U9.U21 ; U9.B18 96.25,61.35 v1(95.85,60.95) ; U11.P12 122.53,68.08 v1(122.13,67.76) ; v1(87.85,68.95) 88.25,69.35 U9.M28 ; U1017.L3 v2(150.66,88.21) ; U9.C8 v1(104.65,61.75) ; U1017.P9 v2(147.66,81.2) ; U1017.M4 v2(149.66,87.21) ; v1(102.25,68.95) 102.65,69.34 U9.M10 ; v1(87.85,70.55) 88.25,70.95 U9.P28 ; U9.C1 v1(110.25,61.75) ; v1(95.85,72.15) 96.25,72.55 U9.T18 ; v1(107.05,80.95) 106.65,80.55 U9.AF5 ; 119.63,35.55 v1(119.11,36.08) ; 119.63,35.55 v1(120.16,36.08) ; 119.63,35.55 C3049.2 ; v1(107.85,81.75) 107.45,81.35 U9.AG4 ; v1(104.65,70.55) 104.25,70.95 U9.P8 ; U9.Y19 95.46,75.75 v1(95.06,76.15) ; Y2000.4 46.94,46.4 47.12,46.22 v2(47.12,46.21) ; U9.J21 93.85,66.95 v1(93.45,66.55) ; U9.AC10 102.65,78.15 v1(103.05,78.55) ; U9.U5 106.65,73.35 v1(107.05,73.75) ; v1(95.85,70.55) 96.25,70.95 U9.P18 ; v1(98.25,63.35) 98.65,63.75 U9.E15 ; U11.D4 U11.C5 128.13,60.93 127.75,60.93 v1(127.56,60.74) ; v1(97.45,60.14) 97.85,60.54 U9.A16 ; v1(130.13,59.96) 129.73,59.63 U11.A3 ; C1047.1 198.12,103.75 v2(198.25,103.62) ; U9.R17 97.05,71.75 v1(96.65,71.35) ; U9.AH20 94.65,82.15 v1(94.25,82.55) ; U9.T10 102.65,72.55 v1(103.05,72.15) ; U9.J23 92.25,66.95 v1(91.85,66.55) ; v1(104.65,72.15) 104.25,72.55 U9.T8 ; v1(97.45,75.35) 97.85,74.95 U9.W16 ; v1(100.65,64.95) 100.25,65.35 U9.G13 ; v1(101.45,80.15) 101.05,79.75 U9.AE12 ; v1(99.86,72.94) 99.46,72.54 U9.T14 ; U11.V5 128.13,70.68 v1(127.73,70.36) ; U129.3 v2(54.63,52.81) ; U11.V12 122.53,70.68 v1(122.93,71.01) 123.33,71.33 U11.W11 ; U11.W2 130.53,71.33 v1(130.93,71.66) ; U9.AC13 100.25,78.15 v1(100.65,78.55) ; C2027.2 v2(41.91,38.34) ; v1(97.45,76.95) 97.85,76.55 U9.AA16 ; Q13.S 54.41,58.21 54.36,58.16 v2(54.36,58.21) ; U9.L7 v1(105.45,68.15) ; D3033.2 v1(140.23,17.53) ; U1002.4 v2(161.35,131.37) ; v1(103.05,76.15) 102.65,75.75 U9.Y10 ; U9.N29 87.45,70.15 v1(87.05,69.75) ; U1017.H2 v2(154.66,89.21) ; v1(103.05,83.35) 102.65,82.95 U9.AJ10 ; v1(97.45,83.35) 97.85,82.95 U9.AJ16 ; v1(103.05,74.55) 102.65,74.15 U9.V10 ; v1(94.25,65.75) 94.65,66.15 U9.H20 ; C3063.2 121.89,24.61 v1(122.66,23.85) ; R1003.2 v2(168.02,131.94) ; U9.D4 v1(107.85,62.55) ; U9.D10 102.65,62.95 v1(103.05,62.55) ; D3030.2 v1(131.02,17.55) ; v1(125.33,67.76) 124.93,67.43 U11.N9 ; v2(43.94,50.68) 43.94,50.1 C2037.2 43.18,50.1 v2(43.18,50.68) ; v1(99.05,74.55) 99.45,74.15 U9.V14 ; U9.P10 102.65,70.95 v1(103.05,70.55) ; U9.G11 101.85,65.35 v1(102.25,64.95) ; U9.AA7 105.05,76.55 v1(105.45,76.95) ; U9.K1 v1(110.25,67.35) ; U9.C20 94.65,62.15 v1(94.25,61.75) ; U27.6 132.07,102.09 v1(132.21,102.22) ; U9.AD17 97.05,78.95 v1(96.65,79.35) ; U1017.G6 v2(155.66,84.21) ; R3062.1 131.17,20.1 v1(131.17,21.12) ; U9.L23 92.25,68.55 v1(91.85,68.15) ; v1(104.65,82.55) 104.25,82.15 U9.AH8 ; v1(104.65,80.95) 104.25,80.55 U9.AF8 ; U9.A7 v1(105.45,60.14) ; v1(108.65,69.75) 108.25,70.15 U9.N3 ; v2(192.15,107.05) 192.02,106.92 C1052.1 ; U1017.G8 v2(155.66,82.2) ; R3060.2 v1(95.94,22.43) ; U1027.6 153.18,59.43 152.65,59.95 U1027.9 ; v1(123.73,63.86) U11.G10 ; U29.36 73.68,106.17 73.91,105.93 v2(76.45,106.42) 73.91,104.92 73.67,105.17 U29.38 ; v1(101.45,74.55) 101.05,74.15 U9.V12 ; D3020.2 v1(134.07,19.2) ; U18.3 v2(68.94,46.62) ; v2(174.62,100.32) v2(173.61,100.32) C1044.2 ; U1017.H9 v2(154.66,81.2) ; v1(97.45,68.95) 97.85,69.35 U9.M16 ; U11.E8 v1(126.13,61.91) ; v1(98.25,76.15) 98.65,75.75 U9.Y15 ; R3149.2 v2(58.67,95.49) ; v1(103.05,80.15) 102.65,79.75 U9.AE10 ; J1011.16 48.19,58.6 48.26,58.66 ; v1(103.85,75.35) 103.45,74.95 U9.W9 ; 128.13,71.98 U11.Y5 ; 128.13,71.98 127.88,72.23 v1(127.67,72.23) ; U1008.14 v2(178.69,52.19) ; v1(104.65,76.15) 104.25,75.75 U9.Y8 ; U9.L21 93.85,68.55 v1(93.45,68.15) ; C1059.1 v2(182.25,54.22) ; U9.E12 v1(101.45,63.35) ; v2(172.59,100.32) v2(171.07,100.32) v2(169.93,100.32) ; 50.55,69.08 50.56,69.1 J1011.57 ; C1023.2 v2(156.08,20.12) ; v1(94.25,68.95) 94.65,69.35 U9.M20 ; v1(103.05,81.75) 102.65,81.35 U9.AG10 ; 131.57,94.63 U27.36 ; U11.V8 125.73,70.68 v1(125.33,70.36) ; 125.73,71.98 124.93,71.33 U11.W9 ; 125.73,71.98 U11.Y8 ; 125.73,71.98 v1(126.13,72.31) ; U9.C17 97.05,62.15 v1(96.65,61.75) ; R3059.2 v1(90.17,35.36) ; U9.K22 93.05,67.75 v1(92.65,67.35) ; 112.12,19.69 C3071.2 112.12,20.45 v1(112.19,20.52) ; v1(110.25,70.55) 109.85,70.95 U9.P1 ; R3151.2 v2(58.67,98.16) ; U9.AF11 101.85,80.55 v1(102.25,80.95) ; U9.H18 96.25,66.15 v1(95.85,65.75) ; v2(166.59,125.68) 167.06,125.21 R1009.2 ; U11.G3 v1(130.13,63.86) ; v2(77.72,68.49) 78.26,68.49 78.77,67.99 R87.2 ; C3145.2 v2(58.29,46.6) ; U11.C1 v1(130.93,61.26) U11.D2 ; U9.B3 v1(108.65,60.95) ; v1(125.32,61.91) 125.32,61.91 124.93,61.59 U11.D9 125.73,60.93 U11.C8 ; R3067.2 v1(112.65,15.11) ; U9.F4 v1(107.85,64.15) ; U1017.M7 v2(150.65,84.2) ; DS1000.1 v2(148.11,11.78) ; v1(91.19,90.9) C53.2 v1(90.5,90.9) ; v1(97.45,65.75) 97.85,66.15 U9.H16 ; U9.J7 105.05,66.95 v1(105.45,66.55) ; v1(132.57,100.67) U27.5 ; v1(97.45,62.55) 97.85,62.95 U9.D16 ; U9.Y17 97.05,75.75 v1(96.65,76.15) ; v1(102.25,82.55) 101.85,82.15 U9.AH11 ; U11.T3 129.73,69.38 v1(129.33,69.71) ; v1(98.25,64.95) 98.65,65.35 U9.G15 ; C1209.1 v2(138.05,149.34) ; v1(88.9,92.57) C42.2 v1(88.14,92.57) ; U9.U17 v1(96.65,73.75) ; v1(94.26,77.75) 94.66,77.35 U9.AB20 ; v1(103.85,73.75) 103.45,73.35 U9.U9 ; U9.C5 v1(107.05,61.75) ; D2.2 v2(159.99,95.75) ; v1(128.53,65.16) U11.K4 ; U11.Y12 122.53,71.98 v1(122.13,72.31) ; U9.L13 v1(100.65,68.15) ; v1(93.45,72.15) 93.85,72.55 U9.T21 ; C1190.2 v2(146.18,58.28) ; U1017.P2 v2(147.66,89.21) ; U9.K8 v1(104.65,67.35) ; U9.AE16 97.85,79.75 v1(97.45,80.15) ; U9.H6 v1(106.25,65.75) ; v1(131.73,69.06) 131.33,69.38 U11.T1 ; v1(107.85,70.55) 107.45,70.95 U9.P4 ; U11.J1 v1(131.73,65.16) ; v1(105.84,20.52) 105.61,20.52 105.3,20.22 105.3,19.61 C3068.2 ; U11.A10 v1(124.13,59.09) ; D3021.2 v1(137.31,19.2) ; v1(96.65,68.15) 97.05,68.55 U9.L17 ; U9.N7 v1(105.45,69.75) ; v1(95.05,69.75) 95.45,70.15 U9.N19 ; U130.3 v2(57.38,57.24) ; U9.A22 93.05,60.54 v1(92.65,60.14) ; C3057.2 v1(114.81,27.42) ; v1(128.53,67.76) 128.93,67.43 U11.N4 ; U9.K14 v1(99.85,67.35) ; C1022.2 v2(153.73,23.74) ; 95.45,73.35 v1(95.05,73.75) ; U9.L9 v1(103.85,68.15) ; v1(79.72,105.17) U29.5 ; v1(96.65,80.95) 97.05,80.55 U9.AF17 ; C173.2 v2(72.77,42.66) ; R1005.2 v2(168.02,129.66) ; U11.E12 v1(122.93,61.91) U11.D11 ; U9.AA18 96.26,76.55 v1(95.86,76.95) ; U9.E1 v1(110.25,63.35) ; v1(96.65,64.95) 97.05,65.35 U9.G17 ; v1(98.25,66.55) 98.65,66.95 U9.J15 ; U9.H10 v1(103.05,65.75) ; U1017.G9 v2(155.66,81.2) ; U9.L15 98.65,68.55 v1(98.25,68.15) ; U9.D7 105.05,62.95 v1(105.45,62.55) ; U9.E5 v1(107.05,63.35) ; U9.K10 v1(103.05,67.35) ; U11.G8 v1(125.33,63.86) ; 48.13,69.08 48.12,69.1 J1011.58 ; U9.W20 v1(94.25,75.35) ; v1(105.45,80.15) 105.05,79.75 U9.AE7 ; v1(100.65,75.35) 100.25,74.95 U9.W13 ; v1(95.85,68.95) 96.25,69.35 U9.M18 ; U9.AF14 99.45,80.55 v1(99.05,80.95) ; v1(106.25,60.95) 105.85,61.35 U9.B6 ; v1(100.65,62.55) 100.25,62.95 U9.D13 ; v1(95.05,71.35) 95.45,71.75 U9.R19 ; v1(123.73,69.06) 124.13,69.38 U11.T10 ; U9.G7 v1(105.45,64.95) ; v1(104.65,64.15) 104.25,64.54 U9.F8 ; v1(97.45,70.55) 97.85,70.95 U9.P16 ; v2(169.93,100.32) C1045.2 ; v2(169.93,100.32) v2(168.78,100.32) ; v1(95.54,25.27) U3011.2 ; U9.AG13 100.25,81.35 v1(100.65,81.75) ; U9.H4 v1(107.85,65.75) ; v1(98.25,73.75) 98.65,73.35 U9.U15 ; D3032.2 v1(137.1,17.55) ; U9.H14 v1(99.85,65.75) ; v1(124.13,73.82) 124.13,73.82 U11.AB10 ; U11.AB3 v1(129.73,73.82) ; U9.K20 94.65,67.75 v1(94.25,67.35) ; R46.1 v2(161.67,109.64) ; U1008.13 177.31,51.02 v2(177.67,50.66) ; U9.H12 v1(101.45,65.75) ; U9.F14 v1(99.85,64.15) ; U1017.G2 v2(155.66,89.21) ; U9.AB8 104.25,77.35 v1(104.65,77.75) ; v2(192.53,101.34) 191.77,101.34 191.52,101.58 U1007.9 189.24,101.58 v2(188.34,102.48) ; U11.K11 v1(123.73,65.16) U11.J10 ; U1017.G4 v2(155.66,87.21) ; v1(111.33,21.89) 111.71,21.52 C3067.2 ; v2(46.35,33) 46.35,33.57 C2023.2 45.59,33.57 v2(45.59,33) ; U9.M6 105.85,69.35 v1(106.25,68.95) ; U1017.G7 v2(155.66,83.21) ; v1(109.45,62.55) 109.05,62.95 U9.D2 ; D3022.2 v1(140.02,19.2) ; v1(100.65,76.95) 100.25,76.55 U9.AA13 ; v1(102.25,79.35) 101.85,78.95 U9.AD11 ; v1(96.65,77.75) 97.05,77.35 U9.AB17 ; U131.3 v2(54.63,50.27) ; U11.N11 123.33,67.43 v1(123.73,67.76) 124.13,68.08 U11.P10 ; U9.C11 v1(102.25,61.75) ; U9.K12 v1(101.45,67.35) ; v1(101.45,70.55) 101.05,70.95 U9.P12 ; v2(175.51,54.22) 175.36,54.07 U1008.10 175.36,50.05 175.58,49.84 175.58,48.57 175.36,48.35 175.36,47.01 175.39,46.98 ; D3031.2 v1(134.39,17.55) ; R1011.2 v2(176.91,125.34) ; U11.T8 125.73,69.38 v1(125.33,69.06) ; R1164.2 v2(140.84,149.09) ; U9.P20 94.65,70.95 v1(94.25,70.55) ; U9.N27 89.05,70.15 v1(88.65,69.75) ; U9.E9 v1(103.85,63.35) ; R1.2 v2(149.35,134.31) ; U9.B21 93.85,61.35 v1(93.45,60.95) ; U9.N17 97.05,70.15 v1(96.65,69.75) ; C1021.2 v2(153.73,21.96) ; v1(98.25,69.75) 98.65,70.15 U9.N15 ; U9.R7 105.05,71.75 v1(105.45,71.35) ; v1(81.28,105.53) 81.14,105.67 U29.6 ; U9.AA14 99.45,76.55 v1(99.05,76.95) ; U9.J9 v1(103.85,66.55) ; D3019.2 v1(131.36,19.2) ; C86.2 v2(161.67,111.17) ; D3034.2 v1(142.94,17.58) ; v2(173.74,56) 173.41,56.32 U1008.22 ; U9.A19 95.45,60.54 v1(95.05,60.14) ; Q1001.1 v2(164.58,122.94) ; v1(98.25,80.15) 98.65,79.75 U9.AE15 ; U9.A10 v1(103.05,60.14) ; U1017.G3 v2(155.66,88.21) ; v1(104.65,74.55) 104.25,74.15 U9.V8 ; C2034.2 v2(41.91,46.6) ; v1(107.05,82.55) 106.65,82.15 U9.AH5 ; D3029.2 v1(128.31,17.55) ; U9.J11 v1(102.25,66.55) ; v1(125.33,65.16) U11.K9 ; U1007.3 192.78,107.05 ; U1017.J5 v2(153.66,86.21) ; U9.R3 108.25,71.75 v1(108.65,71.35) ; U11.C12 v1(122.13,60.61) ; U11.G5 v1(128.53,63.21) ; U11.E1 v1(131.73,62.56) ; RJ1000.3 v2(178.05,132.32) ; U9.AB22 v1(92.65,77.75) ; C206.2 v2(78.77,41.6)
  TOP w0.381: v1(115.7,31.78) 116.5,31.78 ; 116.5,31.78 v1(116.5,31.05) ; 116.5,31.78 C3054.2 ; C3061.2 115.44,24.93 115.44,24.97 ; 104.14,30.23 104.14,30.76 v1(104.52,31.14) ; v1(115.69,25.98) 115.69,25.22 115.44,24.97 ; 115.44,24.97 114.81,25.59 v1(114.81,25.98)
  TOP w0.508: v2(168.15,126.23) 168.66,126.23 C1020.2 168.66,127.24 v2(168.15,127.24) ; v2(168.15,123.69) 168.66,123.69 C1024.2 168.66,124.7 v2(168.15,124.7) ; v2(164.72,132.58) 164.72,132.07 C1012.2 165.74,132.07 v2(165.74,132.58) ; v2(167.13,136.39) 167.64,136.39 C1009.2 167.64,135.37 v2(167.13,135.37) ; v2(167.13,138.8) 167.64,138.8 C1004.2 167.64,137.78 v2(167.13,137.78) ; C1006.1 v2(165.86,135.37) ; C1003.1 v2(168.27,140.2)
  L2-SIGNAL w0.305: v2(174.37,67.17) 174.37,68.06 174.7,68.39 175.06,68.39 175.77,67.68 175.77,65.39 180.97,60.19 184.28,60.19 185.04,59.43 185.04,58.54 184.53,58.03 183.64,58.03 v2(183.39,58.28)
  L4-SIGNAL w0.152: 132.97,76.82 112.39,76.82 110.52,74.95 108.41,74.95 108.25,74.79 108.25,73.5 107.82,73.06 106.92,73.06 106.72,72.86 104.37,72.86 103.85,73.38 v1(103.85,73.75) ; 132.97,76.82 135.51,79.36 135.51,85.59 137.41,87.49 137.41,92.46 136.13,93.74 128.14,93.74 127.53,94.35 127.53,96.58 v1(126.47,97.65) ; 132.97,76.82 133.05,76.75 133.05,70.17 132.21,69.34 132.01,69.34 v1(131.73,69.06) ; v2(132.92,91.26) 132.46,91.26 131.99,91.73 130.24,91.73 129.63,91.13 119.91,91.13 117.58,93.46 117.58,94.21 117.58,101.71 112.74,106.55 102.62,106.55 v2(102.3,106.23) ; v1(131.73,67.76) 133.6,69.63 133.6,69.89 133.63,69.91 133.63,76.69 136.14,79.21 136.14,85.21 v2(137.8,86.86) 137.97,87.04 137.97,93.03 135.66,95.34 135.66,95.77 135.76,95.87 137.12,95.87 v2(137.45,96.2) ; v1(104.65,74.55) 105.05,74.16 106.5,74.16 106.65,74.31 106.65,74.64 106.66,74.65 106.66,74.71 106.89,74.94 106.96,74.94 106.97,74.96 107.22,74.96 107.45,75.19 107.45,75.43 107.46,75.44 107.46,75.51 107.69,75.74 107.76,75.74 107.77,75.76 108.02,75.76 108.25,75.99 108.25,76.23 108.26,76.25 108.26,76.31 108.49,76.54 108.56,76.54 108.56,76.55 110.46,76.55 111.35,77.43 132.72,77.43 134.9,79.62 134.9,85.87 136.65,87.62 136.65,92.32 135.79,93.18 132.05,93.18 131.19,92.32 130.03,92.32 129.4,91.68 120.14,91.68 118.14,93.69 118.14,101.96 112.97,107.13 112.74,107.13 102.17,107.13 101.5,106.46 101.5,106.43 101.35,106.28 v2(101.35,105.65) ; v2(138.39,97.96) 138.67,97.68 139.05,97.68 139.47,97.26 139.47,92.27 140.13,91.61 140.13,91.25 139.88,91 139.5,91 138.85,91.65 138.85,96.39 138.4,96.84 v2(138.39,96.84)
  L6-PWR/GND w0.152: v2(75.89,112.55) 75.89,112.52 75.04,111.67 75.04,111.67 74.5,111.14 73.8,111.14 72.14,109.48 72.14,108.34 72.14,108.33 72.14,108 72.14,108 72.14,101.84 72.14,101.84 72.14,99.03 73.36,97.82 73.36,77.38 76.96,73.78 81.53,73.78 84.71,70.6 85.81,70.6 86.67,69.75 v1(87.05,69.75) ; v1(76.7,111.27) 76.3,110.86 75.83,110.86 75.45,110.48 73.93,110.48 72.69,109.25 72.69,108.57 72.7,108.57 72.7,107.77 72.69,107.76 72.69,103.46 72.7,99.32 73.91,98.1 73.91,77.85 77.23,74.54 81.66,74.54 84.99,71.21 86.36,71.21 86.64,70.93 92.94,70.93 93.04,71.03 93.04,71.57 93.2,71.73 94.67,71.73 v1(95.05,71.35)
  BOTTOM w0.102: C311.2 95.05,73.75 v1(95.05,73.75) ; C452.2 102.32,68.88 v1(102.25,68.95) ; C429.2 v1(101.46,68.93)
  BOTTOM w0.152: C371.2 95.77,65.67 v1(95.85,65.75) ; 111.59,79.38 R218.2 111.59,79.45 v2(111.84,79.7) ; R234.2 98.33,64.87 v1(98.25,64.95) ; C396.2 94.3,57.64 v1(94.23,57.57)
  BOTTOM w0.203: C292.2 100.65,75.35 v1(100.65,75.35) ; v1(97.45,65.75) 97.45,65.58 C446.2 ; v1(103.05,70.55) 103.05,70.47 C427.2 ; R515.1 v2(63.3,106.54)
  BOTTOM w0.254: R1126.1 158.62,131.43 ; U1000.3 U1000.8 v2(180.47,140.58) ; U3021.3 U3021.8 v2(155.83,140.58)
  BOTTOM w0.305: C388.2 121.41,61.32 v1(122.13,60.61) ; 116.2,18.54 C3105.2 ; R3134.2 v2(55.12,20.06) ; R238.2 99.63,61.97 v1(99.85,61.75) ; C413.2 v2(84.02,45.92) ; v1(116.62,24) 115.87,24 ; 115.87,24 C3102.2 ; 115.87,24 114.73,24 ; U3019.2 113.68,26.52 v1(113.93,26.77) 113.68,27.02 U3019.1 ; C3101.2 101.75,24.79 101.22,25.32 v1(101.22,26.31) ; R1143.2 v2(198.25,103.62) ; v1(126.13,73.76) 126.19,73.82 C303.2 ; C2126.2 48.59,48.58 v2(48.84,48.58) ; v2(152.91,32.76) v2(151.51,32.76) D1018.1 149.81,31.05 v2(149.1,30.34) v2(149.1,31.87) 149.47,32.24 149.59,32.24 v2(150.11,32.76) ; C386.2 131.95,64.08 v1(131.73,63.86) ; v1(110.25,61.75) 110.69,61.31 C390.2 ; R3103.1 v1(102.21,21.74) ; v1(131.73,69.06) 131.92,68.87 C345.2 ; C1239.2 v2(158.75,89.78) ; R225.2 106.27,72.71 ; 106.27,72.71 106.73,72.71 107.05,73.03 v1(107.05,73.75) ; 106.27,72.71 105.46,72.71 C316.2 105.08,72.66 C318.2 ; C503.1 v2(137.8,86.86) C506.1 ; v1(113.93,23.77) 113.68,24.02 U3019.7 ; v1(113.93,23.77) 113.68,23.52 U3019.8 ; v1(113.93,23.77) 114.16,24 114.73,24 ; C3100.2 111.92,29.03 ; 111.92,29.03 111.83,28.95 U3019.63 ; 111.92,29.03 111.92,29.58 v1(111.76,29.74) ; C1199.2 v3(187.71,121.27) ; v2(147.66,81.2) 147.34,80.89 C1249.2 ; C3096.2 104.77,30.23 ; 104.77,30.23 104.78,30.23 ; 104.77,30.23 103.46,30.23 ; R3141.2 v2(154.81,90.54) ; C341.2 121.93,69.25 v1(122.13,69.06) ; v2(45.95,41.77) 45.19,42.53 C2125.2 ; R3067.2 v1(112.65,15.11) ; C393.2 124.13,59.09 v1(124.13,59.09) ; 158.62,127.88 v2(157.86,127.88) ; C2119.2 v2(47.37,34.91) ; C1197.2 v2(161.67,125.97) ; U3019.6 113.68,24.52 113.83,24.66 v1(113.92,24.66) 113.57,25.02 U3019.5 ; C2115.2 v2(36.2,28.18) ; C384.2 121.92,64.3 v1(122.13,64.51) ; v2(155.66,81.2) 155.32,80.86 C1240.2 ; 163.32,127.88 v2(163.32,128.7) ; C2127.2 46.99,46.34 47.12,46.22 v2(47.12,46.21) ; v1(105.84,20.52) 106.34,20.03 U3019.29 ; R3111.2 v2(103.25,16.37) ; C3098.2 113.16,30.38 v1(112.9,30.63) ; v2(76.88,43.54) 76.88,43.58 76.91,43.61 76.91,43.63 U24.E5 ; C2118.2 v2(44.58,34.91) ; v2(132.33,104.83) 132.72,104.45 C3146.2 ; U24.B3 v2(79.75,46.46) ; C2120.2 v2(36.2,33.77) 36.96,33.01 RJ2008.3 ; C3114.2 v1(110.36,15.11) ; v1(128.13,73.82) 128.06,73.89 C302.2 ; 114.73,24 C3103.2 ; R2107.2 v2(33.66,36.57) ; C203.2 v2(64.42,106.53) ; C1238.2 v2(159.13,85.59) ; U3019.62 111.34,26.02 v1(111.33,26.01) ; v1(130,11.51) 130,12.7 R3121.1 ; v1(116.28,70.6) 116.58,70.31 R228.2 ; R169.1 v2(149.61,132.98) ; v2(155.66,86.21) 155.32,85.86 C1241.2 ; R1132.2 v2(193.29,117.59) ; v1(130.13,59.96) 130.25,59.83 C392.2 ; R3119.2 132.35,14.71 v1(132.91,15.27) 133.49,14.68 R3118.2 ; C317.2 110.9,71.19 v1(110.25,70.55) ; R204.1 110.95,79.87 111.51,79.87 111.68,79.7 v2(111.84,79.7) ; C3111.2 108.83,16.3 v1(109.56,16.3) ; v2(64.21,102.38) 64.33,102.27 U22.5 ; 103.46,30.23 C3097.2 ; 103.46,30.23 v1(102.74,30.23) ; U1033.2 v2(151.51,93.46) 151.51,93.08 151.24,92.81 U1033.3 ; v1(100.65,78.55) 100.55,78.65 100.05,78.65 R216.2 ; C208.2 v2(60.45,100.88) ; v2(154.66,81.2) 154.35,80.89 C1242.2 ; R3124.2 v2(73.79,19.04) ; U3019.3 113.84,26.02 v1(113.92,25.93) 113.92,25.82 113.61,25.52 U3019.4 ; C2116.2 v2(28.83,33.52) ; U24.C1 v2(81.75,45.46) ; C498.2 v2(130.68,104.83) ; R3110.2 v1(105.03,15.52) ; C2124.2 46.74,39.97 v2(47.24,40.48) ; C2121.2 v2(38.73,36.57) ; 42.93,48.76 v2(42.16,48.76) ; R3128.2 v2(65.53,16.12) ; R1147.1 v2(192.15,107.05) ; U3019.40 v1(105.03,23.02) ; C374.2 v1(132.64,66.08) ; R253.2 v2(83.29,48.8) ; R2103.1 v2(42.54,28.44) ; R2105.1 v2(35.69,31.87) ; R3131.2 v2(62.48,16.12) ; C2129.2 v2(44.96,48.76)
  BOTTOM w0.381: v1(102.62,17.17) 102.62,17.7 102.84,17.93 C3107.2 ; C3108.1 101.71,17.93 v1(101.71,17.21) ; C3110.2 113.92,16.3 v1(114.64,16.3) ; 116.2,18.54 115.06,18.54 C3106.2 ; v1(94.92,17.93) 94.92,17.04 C3109.1 ; v1(98.42,18.4) FL3026.2 v1(98.42,15.68) ; U3020.2 v1(98.58,21.18)
  BOTTOM w0.508: C1245.1 v2(151,95.49)
  vias: v1(61.85,27.29) v1(61.89,25.9) v1(61.85,24.5) v1(63.12,28.56) v1(63.12,27.29) v1(63.16,25.9) v1(63.12,24.5) v1(63.12,23.23) v1(64.52,28.52) v1(64.52,27.26) v1(64.52,25.9) v1(64.52,24.54) v1(64.52,23.27) v1(65.88,25.9) v1(65.91,28.56) v1(65.91,27.29) v1(65.91,24.5) v1(65.91,23.23) v1(67.18,27.29) v1(67.14,25.9) v1(67.18,24.5) v1(77.73,70.6) v1(78.23,85.97) v1(78.23,85.21) v1(78.23,82.16) v1(78.23,81.4) v1(81.07,85.59) v1(81.07,81.78) v1(81.53,79.24) v1(81.53,78.48) v1(81.53,75.81) v1(81.53,75.05) v1(81.53,70.98) v1(81.53,70.22) v1(83.49,85.61) v1(83.61,81.78) v1(83.86,75.81) v1(83.86,75.05) v1(83.91,79.24) v1(83.91,78.6) v1(84.07,89.22) v1(85.34,89.22) v1(86.23,129.71) v1(86.23,126.56) v1(86.23,52.82) v1(86.23,50.41) v1(86.61,89.22) v1(86.61,54.39) v1(87,52.82) v1(87,50.41) v1(87.88,129.71) v1(87.88,89.22) v1(88.01,126.56) v1(88.52,54.39) v1(88.77,129.71) v1(88.77,126.56) v1(89.1,121.4) v1(90.04,52.57) v1(90.04,50.41) v1(90.42,129.71) v1(90.42,54.39) v1(90.55,126.56) v1(90.55,88.76) v1(90.81,52.57) v1(90.81,50.41) v1(90.98,121.4) v1(91.31,129.71) v1(91.31,126.56) v1(91.31,88.76) v1(92.46,101.84) v1(92.58,95.49) v1(92.96,129.71) v1(92.91,121.4) v1(93.09,126.56) v1(93.09,115.18) v1(93.22,85.33) v1(93.34,110.1) v1(93.34,105.02) v1(93.85,129.71) v1(93.85,126.56) v1(93.97,90.92) v1(93.95,88.76) v1(94.03,93.21) v1(94.49,54.47) v1(94.79,121.4) v1(94.73,93.21) v1(94.74,90.92) v1(94.74,88.76) v1(94.87,87.26) v1(94.87,85.33) v1(94.81,30.65) v1(94.81,29.69) v1(94.81,28.72) v1(94.81,27.76) v1(95.12,2.18) v1(95.12,1.3) v1(95.25,54.47) v1(95.38,14.12) v1(95.38,13.11) v1(95.5,129.71) v1(95.63,126.56) v1(95.82,30.65) v1(95.82,29.69) v1(95.82,28.72) v1(95.82,27.76) v1(96.01,2.18) v1(96.01,1.3) v1(96.14,115.05) v1(96.14,110.61) v1(96.14,105.53) v1(96.27,100.45) v1(96.27,87.32) v1(96.27,85.33) v1(96.39,129.71) v1(96.39,126.56) v1(96.72,121.4) v1(96.84,30.65) v1(96.84,29.69) v1(96.84,28.72) v1(96.84,27.76) v1(97.66,87.32) v1(97.66,85.33) v1(97.85,30.65) v1(97.85,29.69) v1(97.85,28.72) v1(97.85,27.76) v1(98.04,129.71) v1(98.17,126.56) v1(98.6,121.4) v1(98.75,96.13) v1(98.75,93.59) v1(98.72,91.43) v1(98.75,89.27) v1(98.87,30.65) v1(98.87,29.69) v1(98.87,28.72) v1(98.87,27.76) v1(98.93,129.71) v1(98.93,126.56) v1(98.93,2.18) v1(98.93,1.3) v1(99.06,87.44) v1(99.06,85.41) v1(99.44,96.13) v1(99.44,93.59) v1(99.41,91.43) v1(99.44,89.27) v1(99.69,110.73) v1(99.69,105.65) v1(99.69,14.12) v1(99.69,13.11) v1(99.82,115.69) v1(99.82,2.18) v1(99.82,1.3) v1(100.58,129.71) v1(100.53,121.4) v1(100.58,87.44) v1(100.58,85.41) v1(100.65,68.95) v1(100.71,126.56) v1(101.35,112.64) v1(101.35,107.56) v1(101.47,72.89) v1(101.45,69.74) v1(101.47,35.97) v1(101.47,35.08) v1(101.85,92.32) v1(101.85,89.78) v1(101.98,87.44) v1(101.98,85.33) v1(102.36,54.35) v1(102.36,35.97) v1(102.36,35.08) v1(102.41,121.4) v1(102.44,92.32) v1(102.41,89.78) v1(103.25,35.97) v1(103.25,35.08) v1(103.38,87.37) v1(103.38,85.33) v1(103.89,52.69) v1(104.14,35.97) v1(104.14,35.08) v1(104.29,121.4) v1(104.78,87.37) v1(104.78,85.33) v1(104.95,114.42) v1(105.79,50.41) v1(105.84,26.01) v1(105.84,24.64) v1(105.84,23.27) v1(105.84,21.89) v1(106.17,87.37) v1(106.22,114.42) v1(106.22,113.15) v1(106.86,113.15) v1(107.24,89.22) v1(107.21,26.01) v1(107.21,24.64) v1(107.21,23.27) v1(107.21,21.89) v1(107.21,20.52) v1(107.49,116.32) v1(107.44,55.23) v1(108.08,48.25) v1(108.18,102.48) v1(108.58,26.01) v1(108.58,24.64) v1(108.58,23.27) v1(108.58,21.89) v1(108.58,20.52) v1(108.76,116.32) v1(109.02,89.22) v1(109.4,117.59) v1(109.86,52.82) v1(109.96,26.01) v1(109.96,24.64) v1(109.96,23.27) v1(109.96,21.89) v1(110.03,117.59) v1(110.87,89.22) v1(111.33,24.64) v1(111.33,23.27) v1(112.52,50.15) v1(113.16,58.41) v1(113.16,57.65) v1(113.66,80.51) v1(113.79,54.47) v1(114.45,88.79) v1(114.55,54.47) v1(114.81,47.87) v1(115.21,88.79) v1(115.57,54.47) v1(115.82,58.41) v1(115.82,57.65) v1(116.28,86.22) v1(116.28,84.32) v1(116.28,82.41) v1(116.28,68.06) v1(116.28,61.71) v1(116.33,54.47) v1(116.84,45.96) v1(116.99,88.79) v1(117.35,54.47) v1(117.75,88.79) v1(117.86,86.6) v1(117.86,85.84) v1(117.86,84.7) v1(117.86,83.94) v1(118.11,54.47) v1(119,43.8) v1(118.96,21.98) v1(120.27,86.6) v1(120.27,85.84) v1(120.27,84.7) v1(120.27,83.94) v1(120.27,82.79) v1(120.27,82.03) v1(121.03,41.77) v1(122.1,76.06) v1(122.17,34.41) v1(122.35,57.01) v1(122.38,55.49) v1(123.06,86.6) v1(123.06,85.84) v1(123.06,39.74) v1(123.52,77.97) v1(123.57,21.2) v1(124.25,76.06) v1(124.21,26.15) v1(124.33,32.12) v1(124.54,55.49) v1(124.59,22.47) v1(124.64,57.01) v1(125.31,15.24) v1(125.31,14.22) v1(125.31,13.21) v1(125.55,77.97) v1(125.73,26.91) v1(125.73,18.91) v1(126.2,13.21) v1(126.24,22.98) v1(126.7,55.49) v1(126.79,57.01) v1(127,19.93) v1(127.25,35.68) v1(127.38,23.99) v1(127.43,76.06) v1(127.59,77.97) v1(128.02,28.69) v1(128.52,30.22) v1(128.78,26.41) v1(128.98,55.49) v1(129.21,57.01) v1(129.62,77.97) v1(130.18,33.64) v1(130.56,26.41) v1(130.6,76.06) v1(130.6,74.54) v1(131.27,55.49) v1(131.87,58.28) v1(131.83,24.63) v1(131.95,30.34) v1(131.95,26.41) v1(132.46,56.25) v1(132.46,32.5) v1(132.59,72.2) v1(132.59,60.62) v1(133.22,56.25) v1(133.6,30.6) v1(133.6,24.63) v1(133.73,26.41) v1(134.24,72.44) v1(134.24,69.65) v1(134.37,56.25) v1(134.87,66.08) v1(134.87,62.9) v1(134.87,59.73) v1(134.87,23.1) v1(135,75.43) v1(134.95,58.28) v1(135.13,56.25) v1(135.76,75.43) v1(136.27,57.65) v1(136.52,59.73) v1(136.65,23.1) v1(136.91,73.52) v1(137.03,57.65) v1(137.29,70.01) v1(137.54,65.84) v1(137.67,73.52) v1(137.8,24.75) v1(139.57,24.75) v1(140.72,23.1) v1(142.49,23.1) v1(157.45,131.56) v1(158.72,131.43) v2(20.83,15.99) v2(24.51,16.25) v2(25.27,18.02) v2(25.65,21.96) v2(25.65,21.2) v2(25.65,19.8) v2(25.65,19.04) v2(26.03,18.02) v2(47.24,43.07) v2(47.24,41.77) v2(48.54,41.77) v2(60.83,72.9) v2(60.91,102.37) v2(62.48,38.09) v2(62.74,72.46) v2(62.74,33.14) v2(62.94,102.38) v2(63.58,102.38) v2(63.91,98.56) v2(63.91,97.42) v2(64.52,72.51) v2(64.52,38.09) v2(64.75,99.82) v2(65.66,96.51) v2(65.66,36.44) v2(65.79,103.75) v2(65.79,102.86) v2(65.79,72.2) v2(66.67,96.51) v2(66.67,34.91) v2(66.93,103.75) v2(66.93,102.86) v2(67.69,72.38) v2(67.69,33.39) v2(68.07,103.75) v2(68.07,102.86) v2(68.2,96.51) v2(68.58,31.87) v2(69.22,96.51) v2(69.22,38.09) v2(69.38,104.82) v2(69.38,104.18) v2(69.6,72.2) v2(70.32,104.82) v2(70.32,104.18) v2(70.61,30.34) v2(71.12,36.31) v2(71.88,73.35) v2(71.88,68.49) v2(72.01,33.39) v2(72.64,34.79) v2(74.3,31.87) v2(74.42,108.45) v2(74.42,107.43) v2(74.42,106.42) v2(74.42,105.4) v2(74.42,104.38) v2(74.42,80.01) v2(74.68,117.46) v2(74.68,116.32) v2(74.68,115.18) v2(74.68,97.65) v2(74.68,96.51) v2(74.68,95.37) v2(75.26,113.49) v2(75.26,112.55) v2(75.26,100.28) v2(75.26,99.34) v2(75.44,108.45) v2(75.44,107.43) v2(75.44,106.42) v2(75.44,105.4) v2(75.44,104.38) v2(75.56,117.46) v2(75.56,116.32) v2(75.56,115.18) v2(75.56,97.65) v2(75.56,96.51) v2(75.56,95.37) v2(75.89,113.49) v2(75.89,100.28) v2(75.89,99.34) v2(76.33,79.57) v2(76.45,108.45) v2(76.45,107.43) v2(76.45,105.4) v2(76.45,104.38) v2(77.01,113.49) v2(77.01,112.55) v2(77.01,100.28) v2(77.01,99.34) v2(77.09,38.09) v2(77.34,117.46) v2(77.34,116.32) v2(77.34,115.18) v2(77.34,97.65) v2(77.34,96.51) v2(77.34,95.37) v2(77.34,36.31) v2(77.47,108.45) v2(77.47,107.43) v2(77.47,106.42) v2(77.47,105.4) v2(77.47,104.38) v2(77.65,113.49) v2(77.65,112.55) v2(77.65,100.28) v2(77.65,99.34) v2(77.72,73.19) v2(77.98,34.91) v2(78.23,117.46) v2(78.23,116.32) v2(78.23,115.18) v2(78.23,97.65) v2(78.23,96.51) v2(78.23,95.37) v2(78.49,108.45) v2(78.49,107.43) v2(78.49,106.42) v2(78.49,105.4) v2(78.49,104.38) v2(78.49,33.39) v2(79.25,31.87) v2(81.66,38.09) v2(83.88,109.74) v2(83.88,108.37) v2(83.89,107.05) v2(83.89,105.4) v2(83.89,104) v2(83.89,102.35) v2(84.58,97.65) v2(85.09,38.6) v2(85.34,97.65) v2(85.98,31.1) v2(87,97.65) v2(88,44.57) v2(88.01,41.52) v2(88.14,97.65) v2(88.39,33.39) v2(88.44,46.47) v2(89.41,89.52) v2(90.93,86.43) v2(92.15,100.19) v2(92.16,44.44) v2(92.23,93.84) v2(92.58,91.94) v2(92.58,89.22) v2(92.5,46.34) v2(96.13,44.44) v2(96.14,36.82) v2(96.57,46.34) v2(98.04,38.09) v2(101.26,102.48) v2(101.6,44.44) v2(101.78,46.34) v2(101.85,38.22) v2(104.01,39.74) v2(104.65,119.12) v2(104.65,43.93) v2(105.41,30.47) v2(105.66,33.64) v2(105.79,117.59) v2(106.17,43.42) v2(106.55,37.2) v2(107.73,44.47) v2(107.95,41.14) v2(108.03,100.57) v2(108.03,92.57) v2(108.13,46.34) v2(108.33,94.22) v2(108.71,33.14) v2(108.84,109.21) v2(109.09,123.43) v2(110.24,35.93) v2(110.36,122.16) v2(110.74,38.6) v2(111.12,30.72) v2(112.32,88.78) v2(113.03,42.28) v2(113.92,103.75) v2(114.12,92.7) v2(114.3,94.22) v2(114.81,40.5) v2(115.7,126.35) v2(118.62,107.18) v2(119.63,107.18) v2(120.27,99.18) v2(120.27,98.29) v2(120.27,96.51) v2(120.27,95.62) v2(120.65,126.35) v2(120.65,122.42) v2(121.03,107.18) v2(121.41,99.18) v2(121.41,98.29) v2(121.41,96.51) v2(121.41,95.62) v2(122.05,107.18) v2(122.43,45.96) v2(122.55,99.18) v2(122.55,98.29) v2(122.55,96.51) v2(122.55,95.62) v2(122.73,47.87) v2(123.88,80.41) v2(124.24,98.59) v2(124.24,97.96) v2(124.24,96.84) v2(124.24,96.2) v2(124.89,80.41) v2(125.18,98.59) v2(125.18,97.96) v2(125.18,96.84) v2(125.18,96.2) v2(125.73,126.35) v2(126.36,80.43) v2(126.75,122.54) v2(127.38,80.43) v2(127.99,104.82) v2(129.29,99.43) v2(129.29,98.41) v2(129.29,97.4) v2(129.29,96.38) v2(129.29,95.37) v2(129.36,104.82) v2(130.18,126.48) v2(130.3,99.43) v2(130.3,98.41) v2(130.3,97.4) v2(130.3,96.38) v2(130.3,95.37) v2(131.32,99.43) v2(131.32,98.41) v2(131.32,97.4) v2(131.32,96.38) v2(131.32,95.37) v2(131.83,122.54) v2(132.33,99.43) v2(132.33,98.41) v2(132.33,97.4) v2(132.33,96.38) v2(132.33,95.37) v2(132.5,83.3) v2(132.92,90.32) v2(133.35,99.43) v2(133.35,98.41) v2(133.35,97.4) v2(133.35,96.38) v2(133.35,95.37) v2(133.55,91.26) v2(133.55,90.32) v2(133.73,104.83) v2(133.99,89.02) v2(133.99,87.87) v2(133.99,86.73) v2(134.87,89.02) v2(134.87,87.87) v2(134.87,86.73) v2(135.25,126.48) v2(135.38,104.83) v2(136.09,71.66) v2(136.91,122.54) v2(137.26,64.6) v2(137.45,98.59) v2(137.45,97.96) v2(137.45,96.84) v2(138.39,98.59) v2(138.39,96.2) v2(140.08,99.18) v2(140.08,98.29) v2(140.08,96.51) v2(140.08,95.62) v2(140.33,126.48) v2(141.22,99.18) v2(141.22,98.29) v2(141.22,96.51) v2(141.22,95.62) v2(141.99,122.54) v2(142.37,99.18) v2(142.37,98.29) v2(142.37,96.51) v2(142.37,95.62) v2(145.41,126.48) v2(147.07,122.54) v2(150.5,126.48) v2(152.02,58.92) v2(152.15,122.54) v2(152.91,63.87) v2(153.29,60.06) v2(153.8,133.59) v2(153.8,63.87) v2(154.38,106.54) v2(155.17,106.54) v2(155.32,63.87) v2(155.45,126.23) v2(155.83,133.59) v2(155.96,131.69) v2(156.21,63.87) v2(156.34,120.77) v2(157.35,124.32) v2(157.66,109.57) v2(157.66,108.8) v2(158.12,67.25) v2(159.13,67.25) v2(161.29,120.64) v2(164.34,63.87) v2(165.23,63.87) v2(166.12,63.87) v2(166.37,120.64) v2(167.39,63.87) v2(168.27,63.87) v2(169.16,63.87) v2(170.05,63.87) v2(170.69,123.05) v2(171.32,64.19) v2(171.45,120.64) v2(171.96,56) v2(171.96,55.11) v2(171.96,54.22) v2(172.85,56) v2(172.85,55.11) v2(172.85,54.22) v2(173.35,63.49) v2(173.61,132.45) v2(173.74,55.11) v2(173.74,54.22) v2(174.62,123.05) v2(174.62,56) v2(174.62,55.11) v2(174.62,54.22) v2(175.51,56) v2(175.51,55.11) v2(175.9,62.6) v2(176.53,120.64) v2(178.44,126.99) v2(178.56,133.47) v2(179.83,123.81) v2(180.34,133.47) v2(180.47,128.13) v2(180.59,131.56) v2(180.72,63.87) v2(182.37,131.56) v2(182.5,128.13) v2(182.5,63.87) v2(183.39,63.87) v2(184.53,63.87) v2(185.42,63.87) v2(186.31,63.87) v2(186.31,62.85) v2(189.36,63.87) v2(189.36,62.85) v2(190.25,63.87) v2(191.13,63.87) v2(191.77,102.1) v2(191.77,100.57) v2(192.41,123.18) v2(193.29,102.1) v2(193.29,100.57) v2(193.42,123.18) v2(194.69,123.18) v2(195.83,123.18) v2(197.99,123.18) v3(187.71,120) v3(187.71,118.73) v3(187.71,117.46) v3(188.98,121.27) v3(188.98,120) v3(188.98,118.73) v3(188.98,117.46) v3(190.25,121.27) v3(190.25,120) v3(190.25,118.73) v3(190.25,117.46) v4(22.68,16.25)
